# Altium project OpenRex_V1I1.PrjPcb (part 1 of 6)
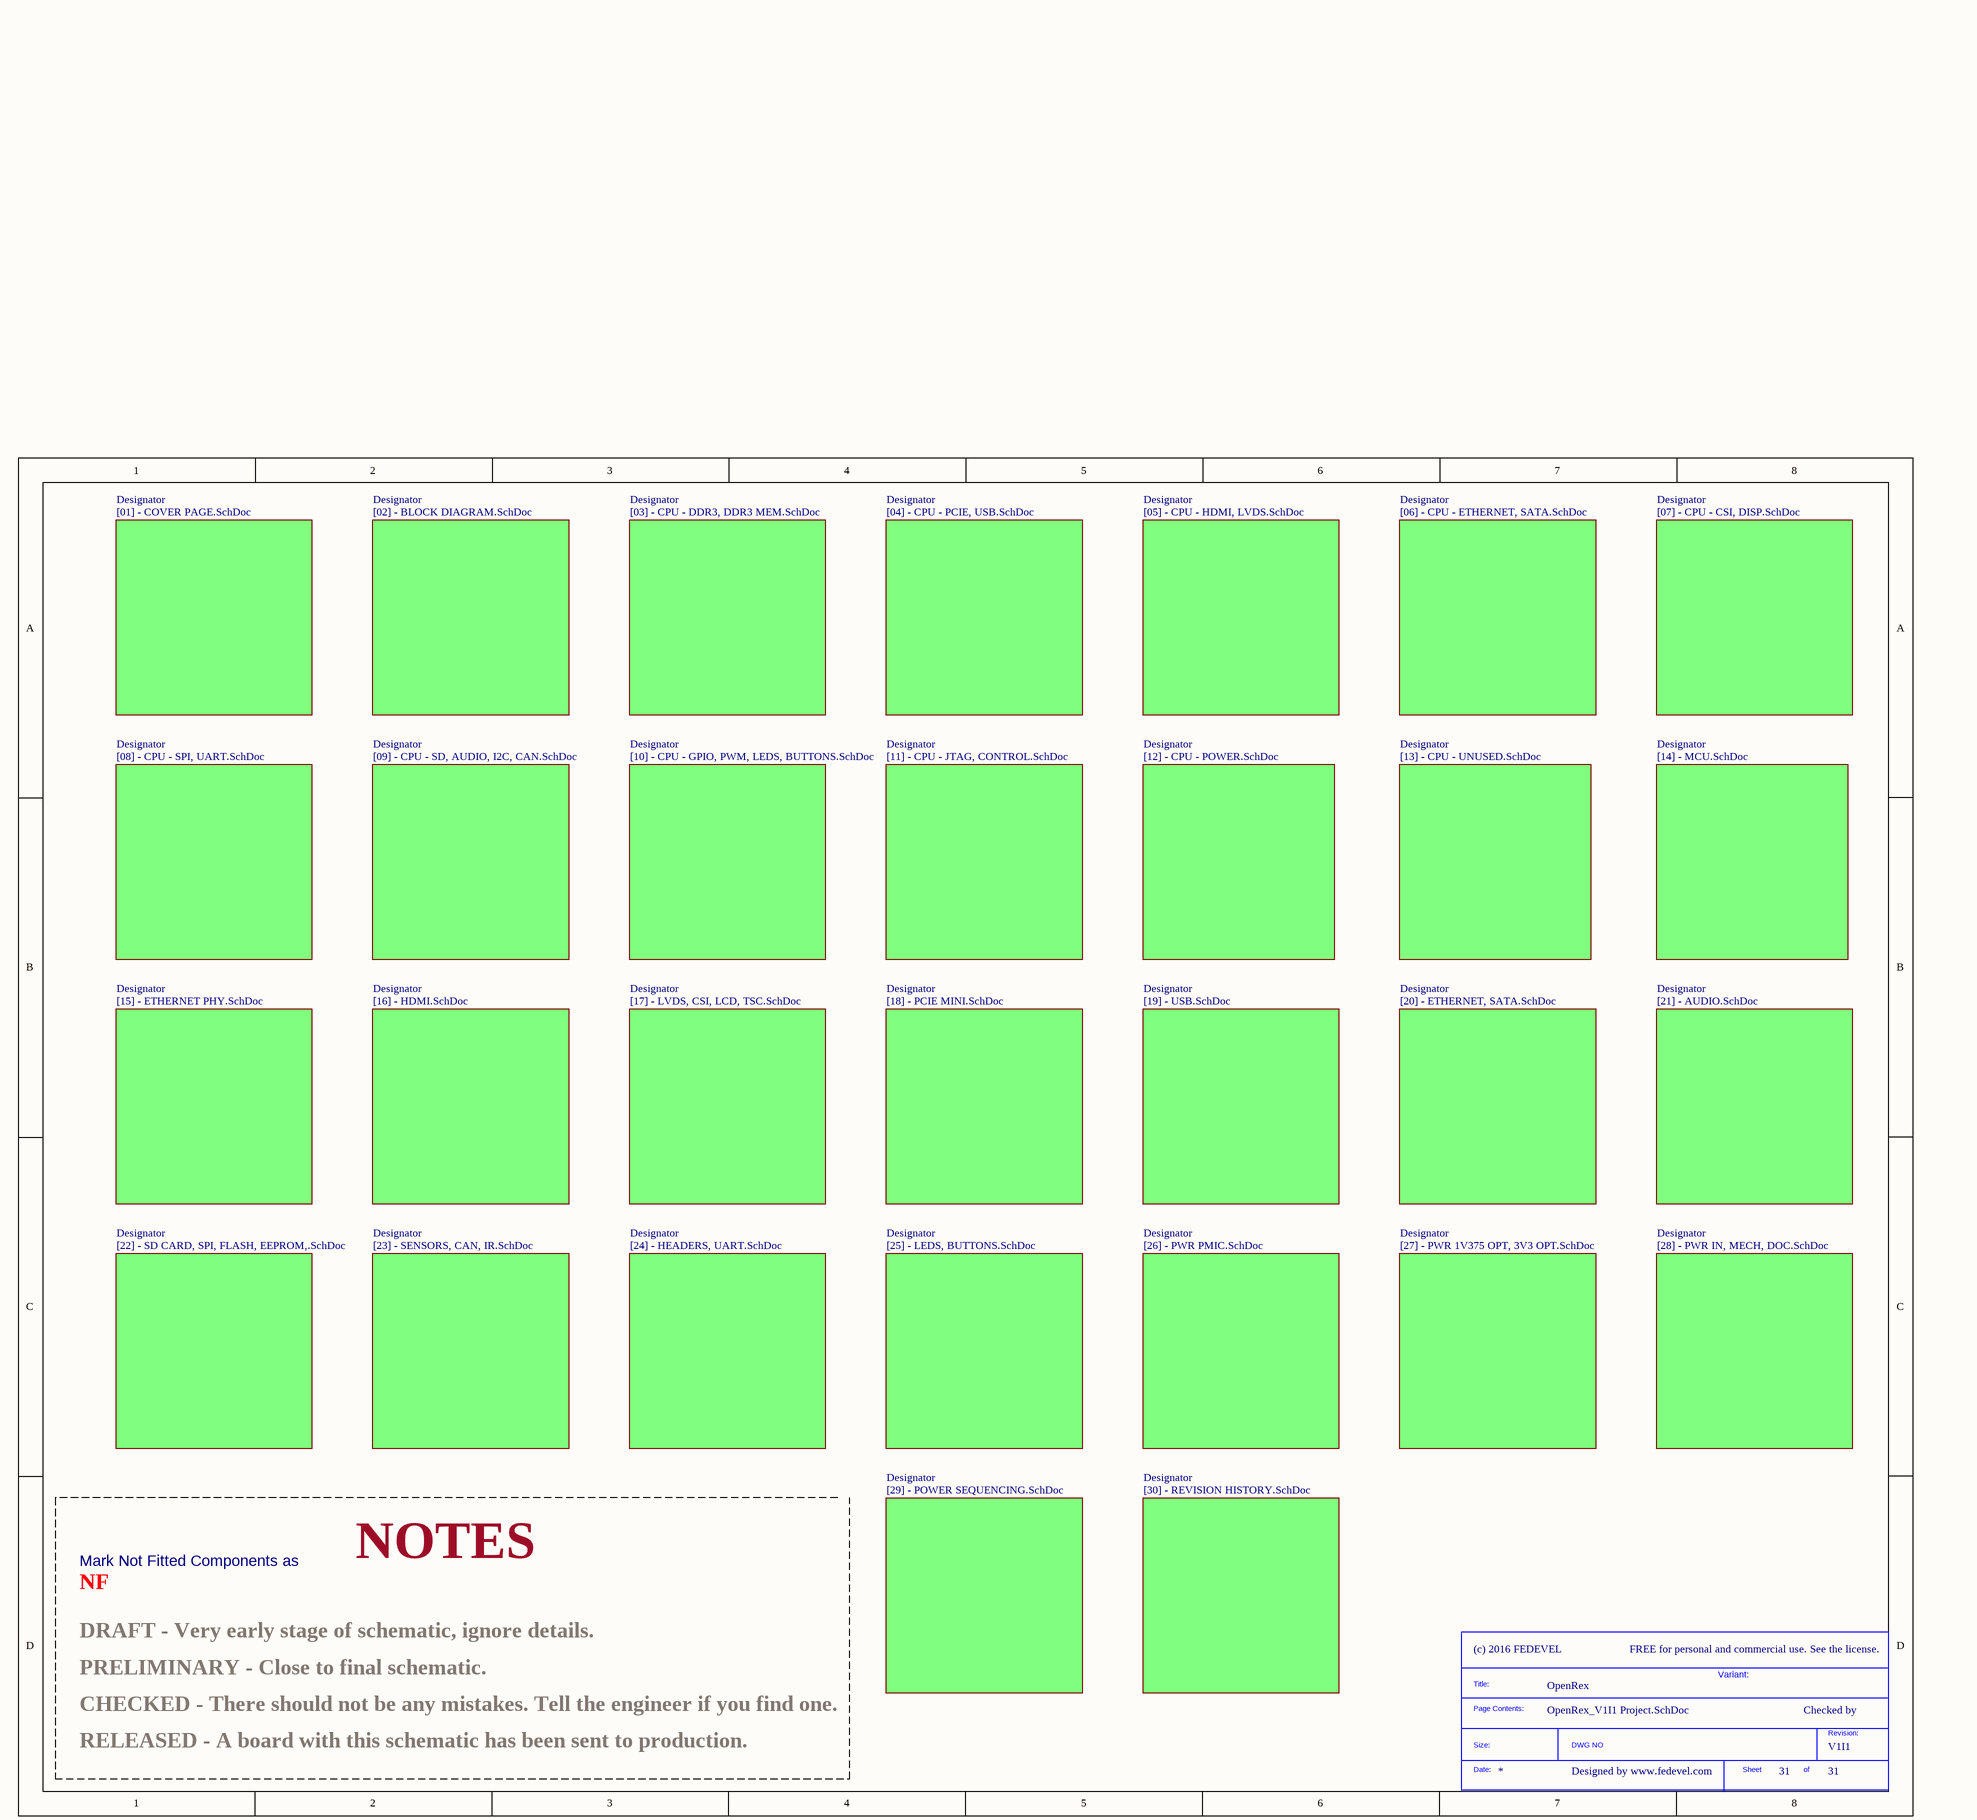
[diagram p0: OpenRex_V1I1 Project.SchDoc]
VersionRevision: V1I1; Project: OpenRex; NotFitted: NF; Company: (c) 2016 FEDEVEL; ClientWebsite: www.fedevel.com; ClientContactName: Robert Feranec; ClientContactEmail: robert.feranec@fedevel.com; ClientCompanyName: FEDEVEL Academy
31 sheets, 1116 parts. Net scope: flat (ports and power ports of the same name join across sheets).
Board file: OpenRex_V1I1_PCB.PcbDoc
Sheets:
  OpenRex_V1I1 Project.SchDoc
    Designator = [01] - COVER PAGE.SchDoc
    Designator = [02] - BLOCK DIAGRAM.SchDoc
    Designator = [17] - LVDS, CSI, LCD, TSC.SchDoc
    Designator = [04] - CPU - PCIE, USB.SchDoc
    Designator = [05] - CPU - HDMI, LVDS.SchDoc
    Designator = [06] - CPU - ETHERNET, SATA.SchDoc
    Designator = [08] - CPU - SPI, UART.SchDoc
    Designator = [10] - CPU - GPIO, PWM, LEDS, BUTTONS.SchDoc
    Designator = [09] - CPU - SD, AUDIO, I2C, CAN.SchDoc
    Designator = [03] - CPU - DDR3, DDR3 MEM.SchDoc
    Designator = [11] - CPU - JTAG, CONTROL.SchDoc
    Designator = [12] - CPU - POWER.SchDoc
    Designator = [18] - PCIE MINI.SchDoc
    Designator = [13] - CPU - UNUSED.SchDoc
    Designator = [15] - ETHERNET PHY.SchDoc
    Designator = [19] - USB.SchDoc
    Designator = [07] - CPU - CSI, DISP.SchDoc
    Designator = [14] - MCU.SchDoc
    Designator = [20] - ETHERNET, SATA.SchDoc
    Designator = [25] - LEDS, BUTTONS.SchDoc
    Designator = [26] - PWR PMIC.SchDoc
    Designator = [27] - PWR 1V375 OPT, 3V3 OPT.SchDoc
    Designator = [28] - PWR IN, MECH, DOC.SchDoc
    Designator = [22] - SD CARD, SPI, FLASH, EEPROM,.SchDoc
    Designator = [23] - SENSORS, CAN, IR.SchDoc
    Designator = [30] - REVISION HISTORY.SchDoc
    Designator = [16] - HDMI.SchDoc
    Designator = [21] - AUDIO.SchDoc
    Designator = [24] - HEADERS, UART.SchDoc
    Designator = [29] - POWER SEQUENCING.SchDoc

## Sheet OpenRex_V1I1 Project.SchDoc
size A3; DocumentNumber: 31; SheetNumber: 31; SheetTotal: 31; PageSetup: Record=PageOptions¦CenterHorizontal=True¦CenterVertical=True¦PrintScale=1.07¦XCorrection=1.00¦YCorrection=1.00¦PrintKind=1¦BorderSize=5000000¦LeftOffset=0¦BottomOffset=0¦Orientation=2¦PaperLength=1000¦PaperWidth=1000¦Scale=100¦PaperSource=7¦PrintQuality=600¦MediaType=1¦DitherType=10¦PaperKind=A3¦PrintScaleMode=1

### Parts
(Parts that share a designator on the sheet are numbered #1, #2 ... from top to bottom, then left to right.)
*#1  SDTitleBlock  (value not drawn)  (graphical)

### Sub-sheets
Designator = [01] - COVER PAGE.SchDoc: no entries
Designator = [02] - BLOCK DIAGRAM.SchDoc: no entries
Designator = [17] - LVDS, CSI, LCD, TSC.SchDoc: no entries
Designator = [04] - CPU - PCIE, USB.SchDoc: no entries
Designator = [05] - CPU - HDMI, LVDS.SchDoc: no entries
Designator = [06] - CPU - ETHERNET, SATA.SchDoc: no entries
Designator = [08] - CPU - SPI, UART.SchDoc: no entries
Designator = [10] - CPU - GPIO, PWM, LEDS, BUTTONS.SchDoc: no entries
Designator = [09] - CPU - SD, AUDIO, I2C, CAN.SchDoc: no entries
Designator = [03] - CPU - DDR3, DDR3 MEM.SchDoc: no entries
Designator = [11] - CPU - JTAG, CONTROL.SchDoc: no entries
Designator = [12] - CPU - POWER.SchDoc: no entries
Designator = [18] - PCIE MINI.SchDoc: no entries
Designator = [13] - CPU - UNUSED.SchDoc: no entries
Designator = [15] - ETHERNET PHY.SchDoc: no entries
Designator = [19] - USB.SchDoc: no entries
Designator = [07] - CPU - CSI, DISP.SchDoc: no entries
Designator = [14] - MCU.SchDoc: no entries
Designator = [20] - ETHERNET, SATA.SchDoc: no entries
Designator = [25] - LEDS, BUTTONS.SchDoc: no entries
Designator = [26] - PWR PMIC.SchDoc: no entries
Designator = [27] - PWR 1V375 OPT, 3V3 OPT.SchDoc: no entries
Designator = [28] - PWR IN, MECH, DOC.SchDoc: no entries
Designator = [22] - SD CARD, SPI, FLASH, EEPROM,.SchDoc: no entries
Designator = [23] - SENSORS, CAN, IR.SchDoc: no entries
Designator = [30] - REVISION HISTORY.SchDoc: no entries
Designator = [16] - HDMI.SchDoc: no entries
Designator = [21] - AUDIO.SchDoc: no entries
Designator = [24] - HEADERS, UART.SchDoc: no entries
Designator = [29] - POWER SEQUENCING.SchDoc: no entries

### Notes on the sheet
- NF
- Mark Not Fitted Components as
- NOTES
- DRAFT - Very early stage of schematic, ignore details.
- FREE for personal and commercial use. See the license.
- PRELIMINARY - Close to final schematic.
- CHECKED - There should not be any mistakes. Tell the engineer if you find one.
- Variant:
- Checked by
- RELEASED - A board with this schematic has been sent to production.
- Designed by www.fedevel.com

## Sheet [01] - COVER PAGE.SchDoc
size A3; DocumentNumber: 1; SheetNumber: 1; SheetTotal: 31
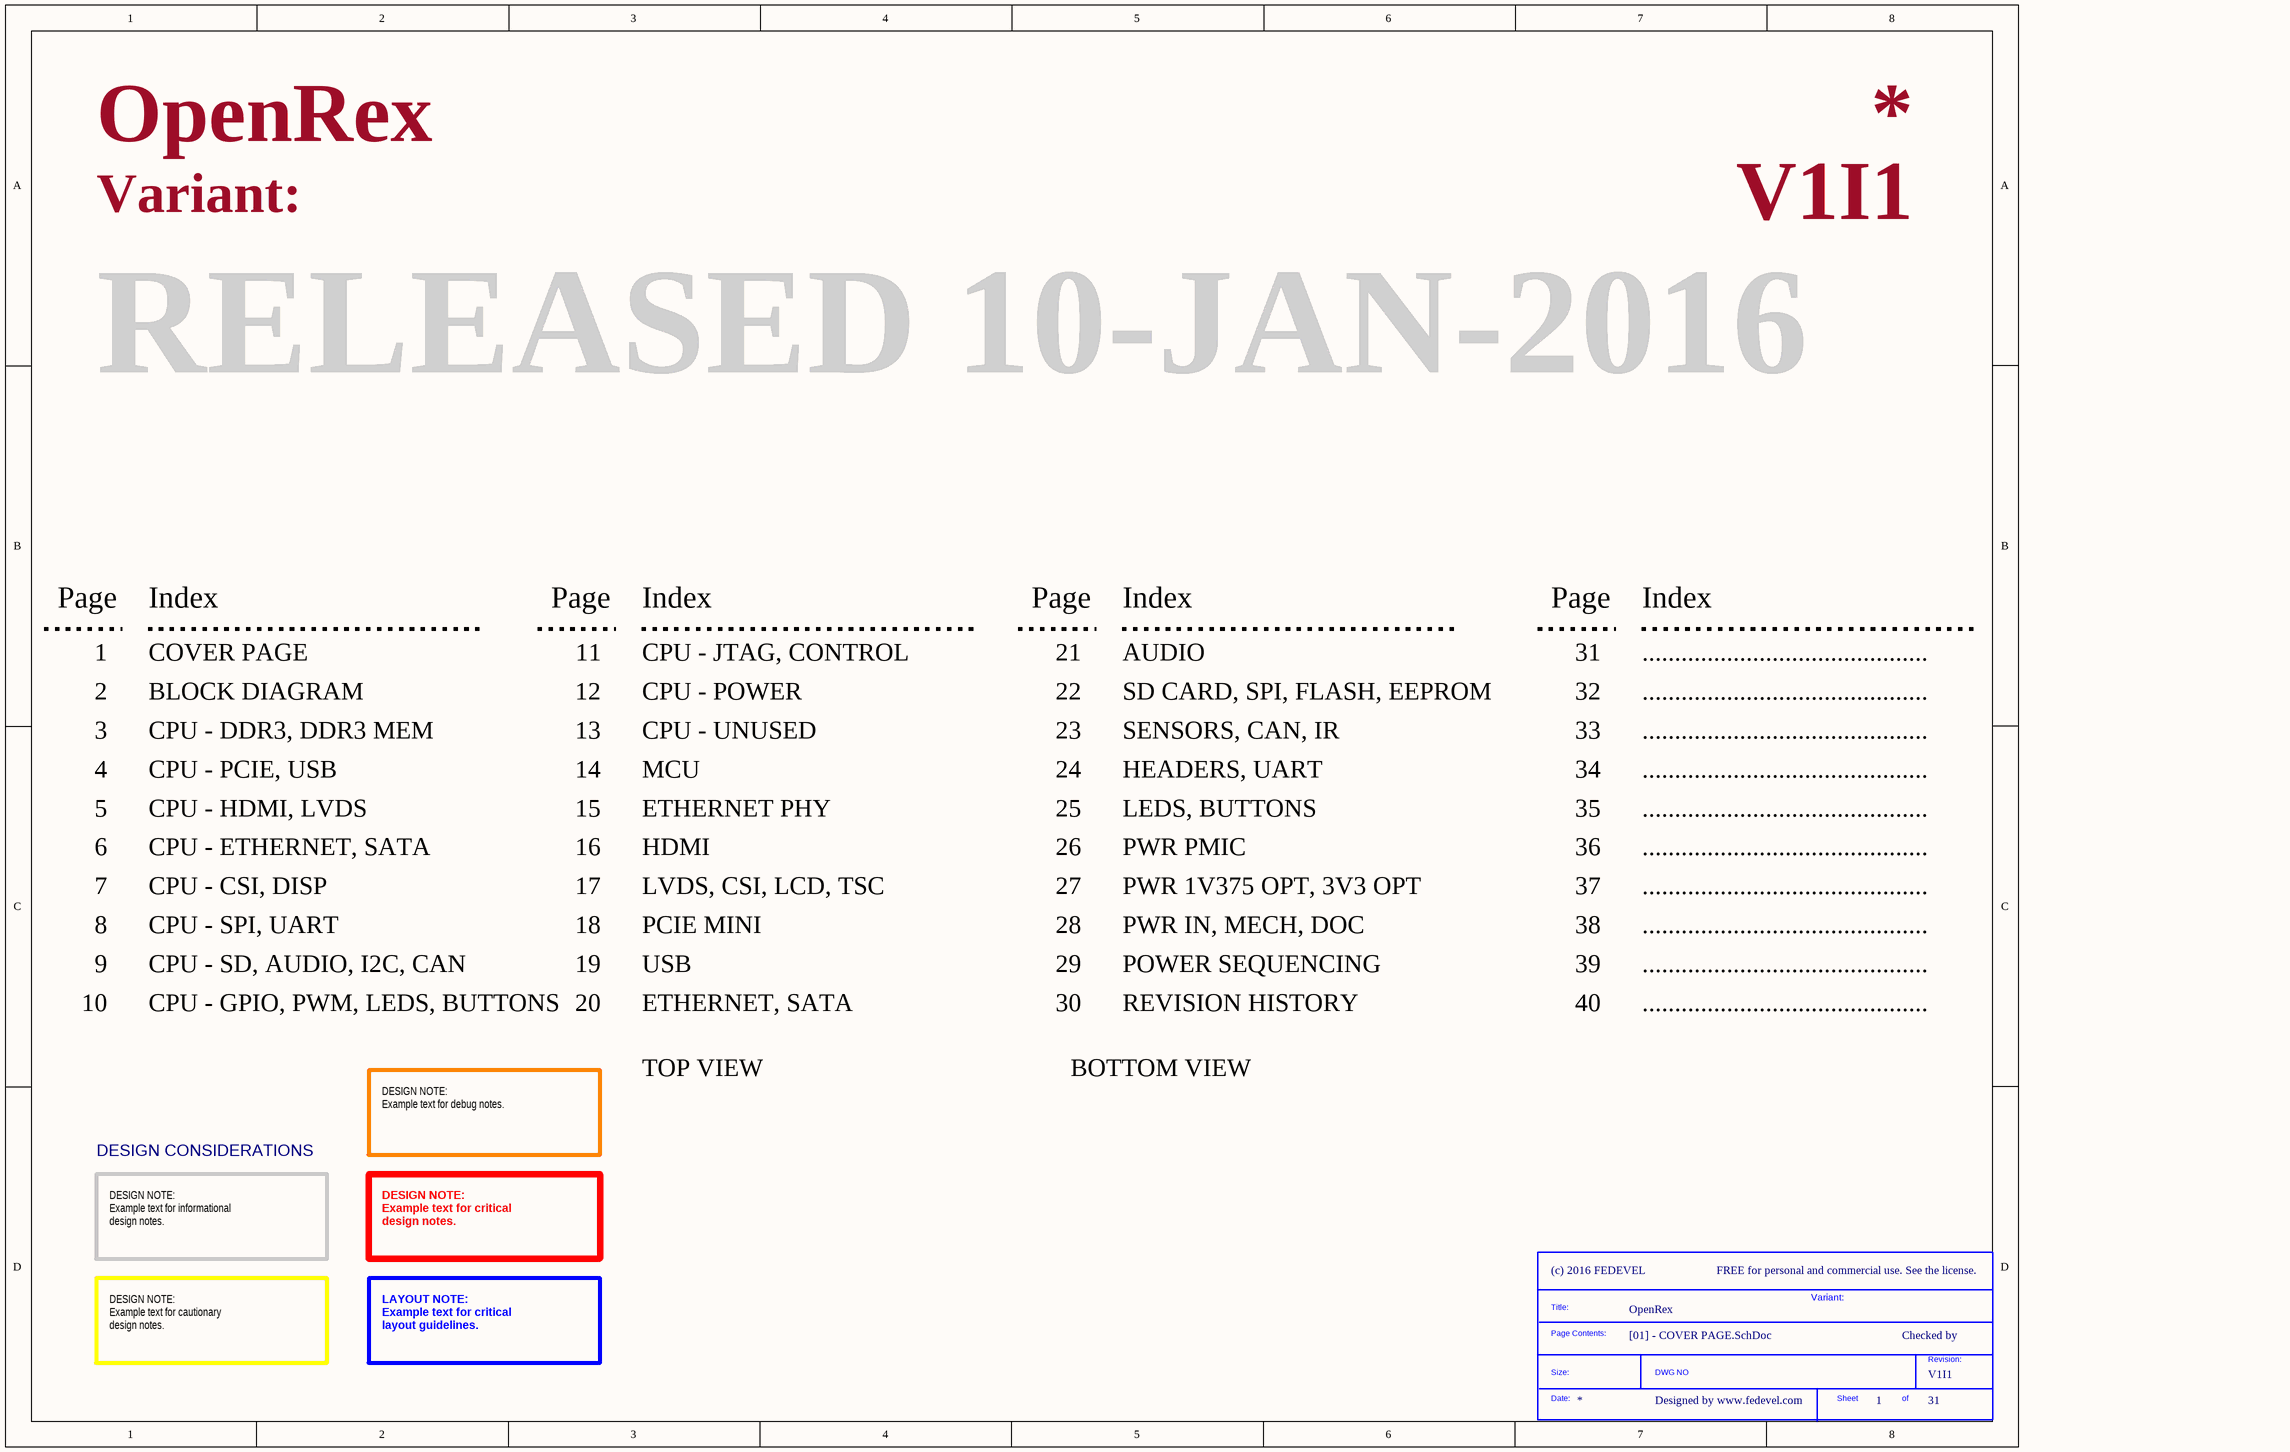
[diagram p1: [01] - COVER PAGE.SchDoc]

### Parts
(Parts that share a designator on the sheet are numbered #1, #2 ... from top to bottom, then left to right.)
*#2  SDTitleBlock  (value not drawn)  (graphical)

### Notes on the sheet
- Variant:
- RELEASED 10-JAN-2016
- Page
- Index
- 1
- COVER PAGE
- 11
- CPU - JTAG, CONTROL
- 21
- AUDIO
- 31
- ............................................
- 2
- 3
- BLOCK DIAGRAM
- CPU - DDR3, DDR3 MEM
- 12
- 13
- CPU - POWER
- CPU - UNUSED
- 22
- 23
- SD CARD, SPI, FLASH, EEPROM
- SENSORS, CAN, IR
- 32
- 33
- 4
- 5
- CPU - PCIE, USB
- CPU - HDMI, LVDS
- 14
- 15
- MCU
- ETHERNET PHY
- 24
- 25
- HEADERS, UART
- LEDS, BUTTONS
- 34
- 35
- 6
- CPU - ETHERNET, SATA
- 16
- HDMI
- 26
- PWR PMIC
- 36
- 7
- 8
- CPU - SPI, UART
- CPU - CSI, DISP
- 17
- 18
- LVDS, CSI, LCD, TSC
- PCIE MINI
- 27
- 28
- PWR 1V375 OPT, 3V3 OPT
- PWR IN, MECH, DOC
- 37
- 38
- 9
- 10
- CPU - SD, AUDIO, I2C, CAN
- CPU - GPIO, PWM, LEDS, BUTTONS
- 19
- 20
- USB
- ETHERNET, SATA
- 29
- 30
- POWER SEQUENCING
- REVISION HISTORY
- 39
- 40
- TOP VIEW
- BOTTOM VIEW
- DESIGN NOTE:
  Example text for debug notes.
- DESIGN CONSIDERATIONS
- DESIGN NOTE:
  Example text for informational
  design notes.
- DESIGN NOTE:
  Example text for critical
  design notes.
- FREE for personal and commercial use. See the license.
- Checked by
- DESIGN NOTE:
  Example text for cautionary
  design notes.
- LAYOUT NOTE:
  Example text for critical
  layout guidelines.
- Designed by www.fedevel.com

## Sheet [02] - BLOCK DIAGRAM.SchDoc
size A2; DocumentNumber: 2; SheetNumber: 2; SheetTotal: 31; PageSetup: Record=PageOptions¦CenterHorizontal=True¦CenterVertical=True¦PrintScale=0.52¦XCorrection=1.00¦YCorrection=1.00¦PrintKind=1¦BorderSize=5000000¦LeftOffset=0¦BottomOffset=0¦Orientation=2¦PaperLength=1000¦PaperWidth=1000¦Scale=100¦PaperSource=4¦PrintQuality=600¦MediaType=1¦DitherType=10¦PrintScaleMode=1¦PaperKind=A4¦PaperIndex=9
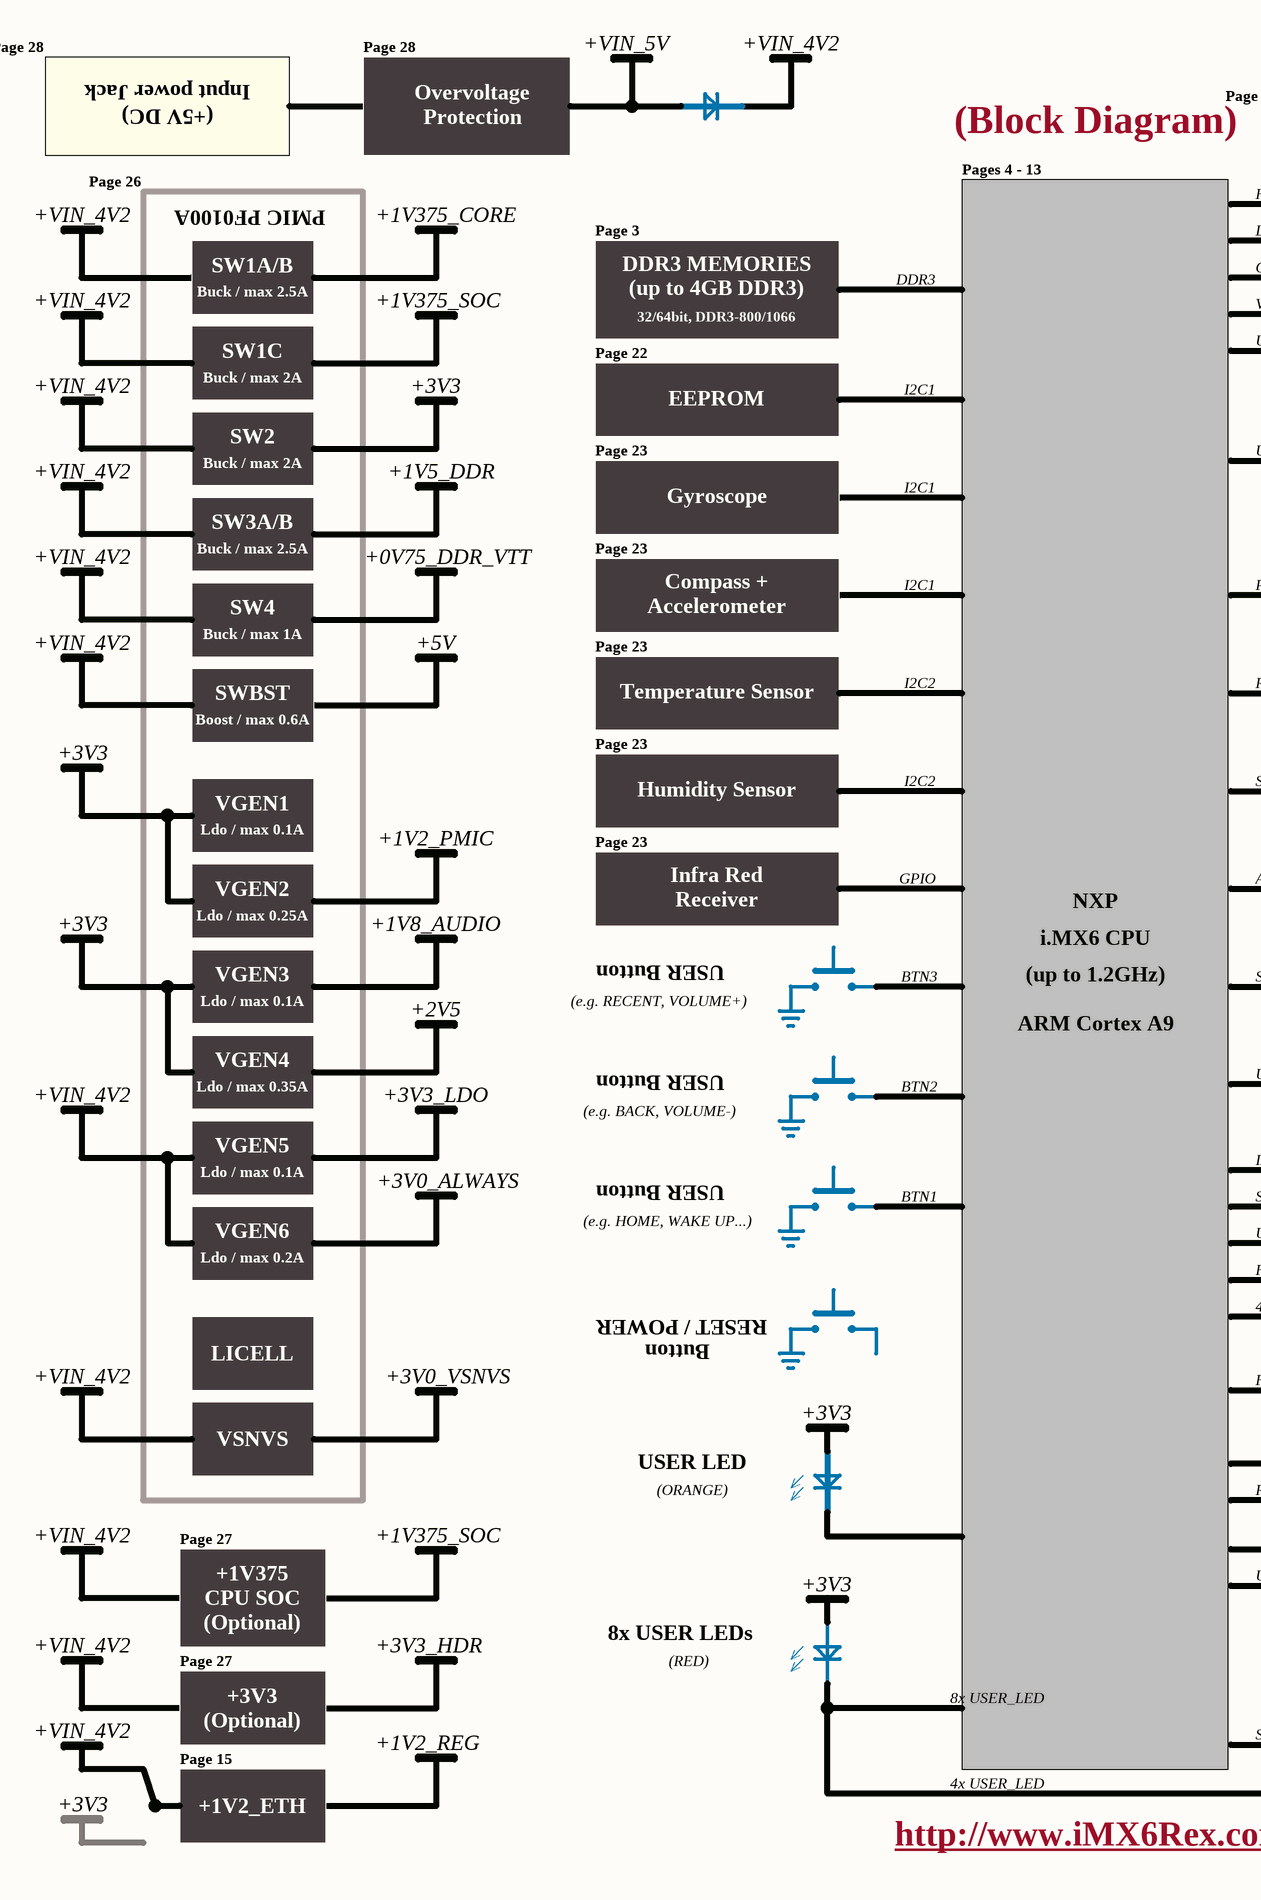
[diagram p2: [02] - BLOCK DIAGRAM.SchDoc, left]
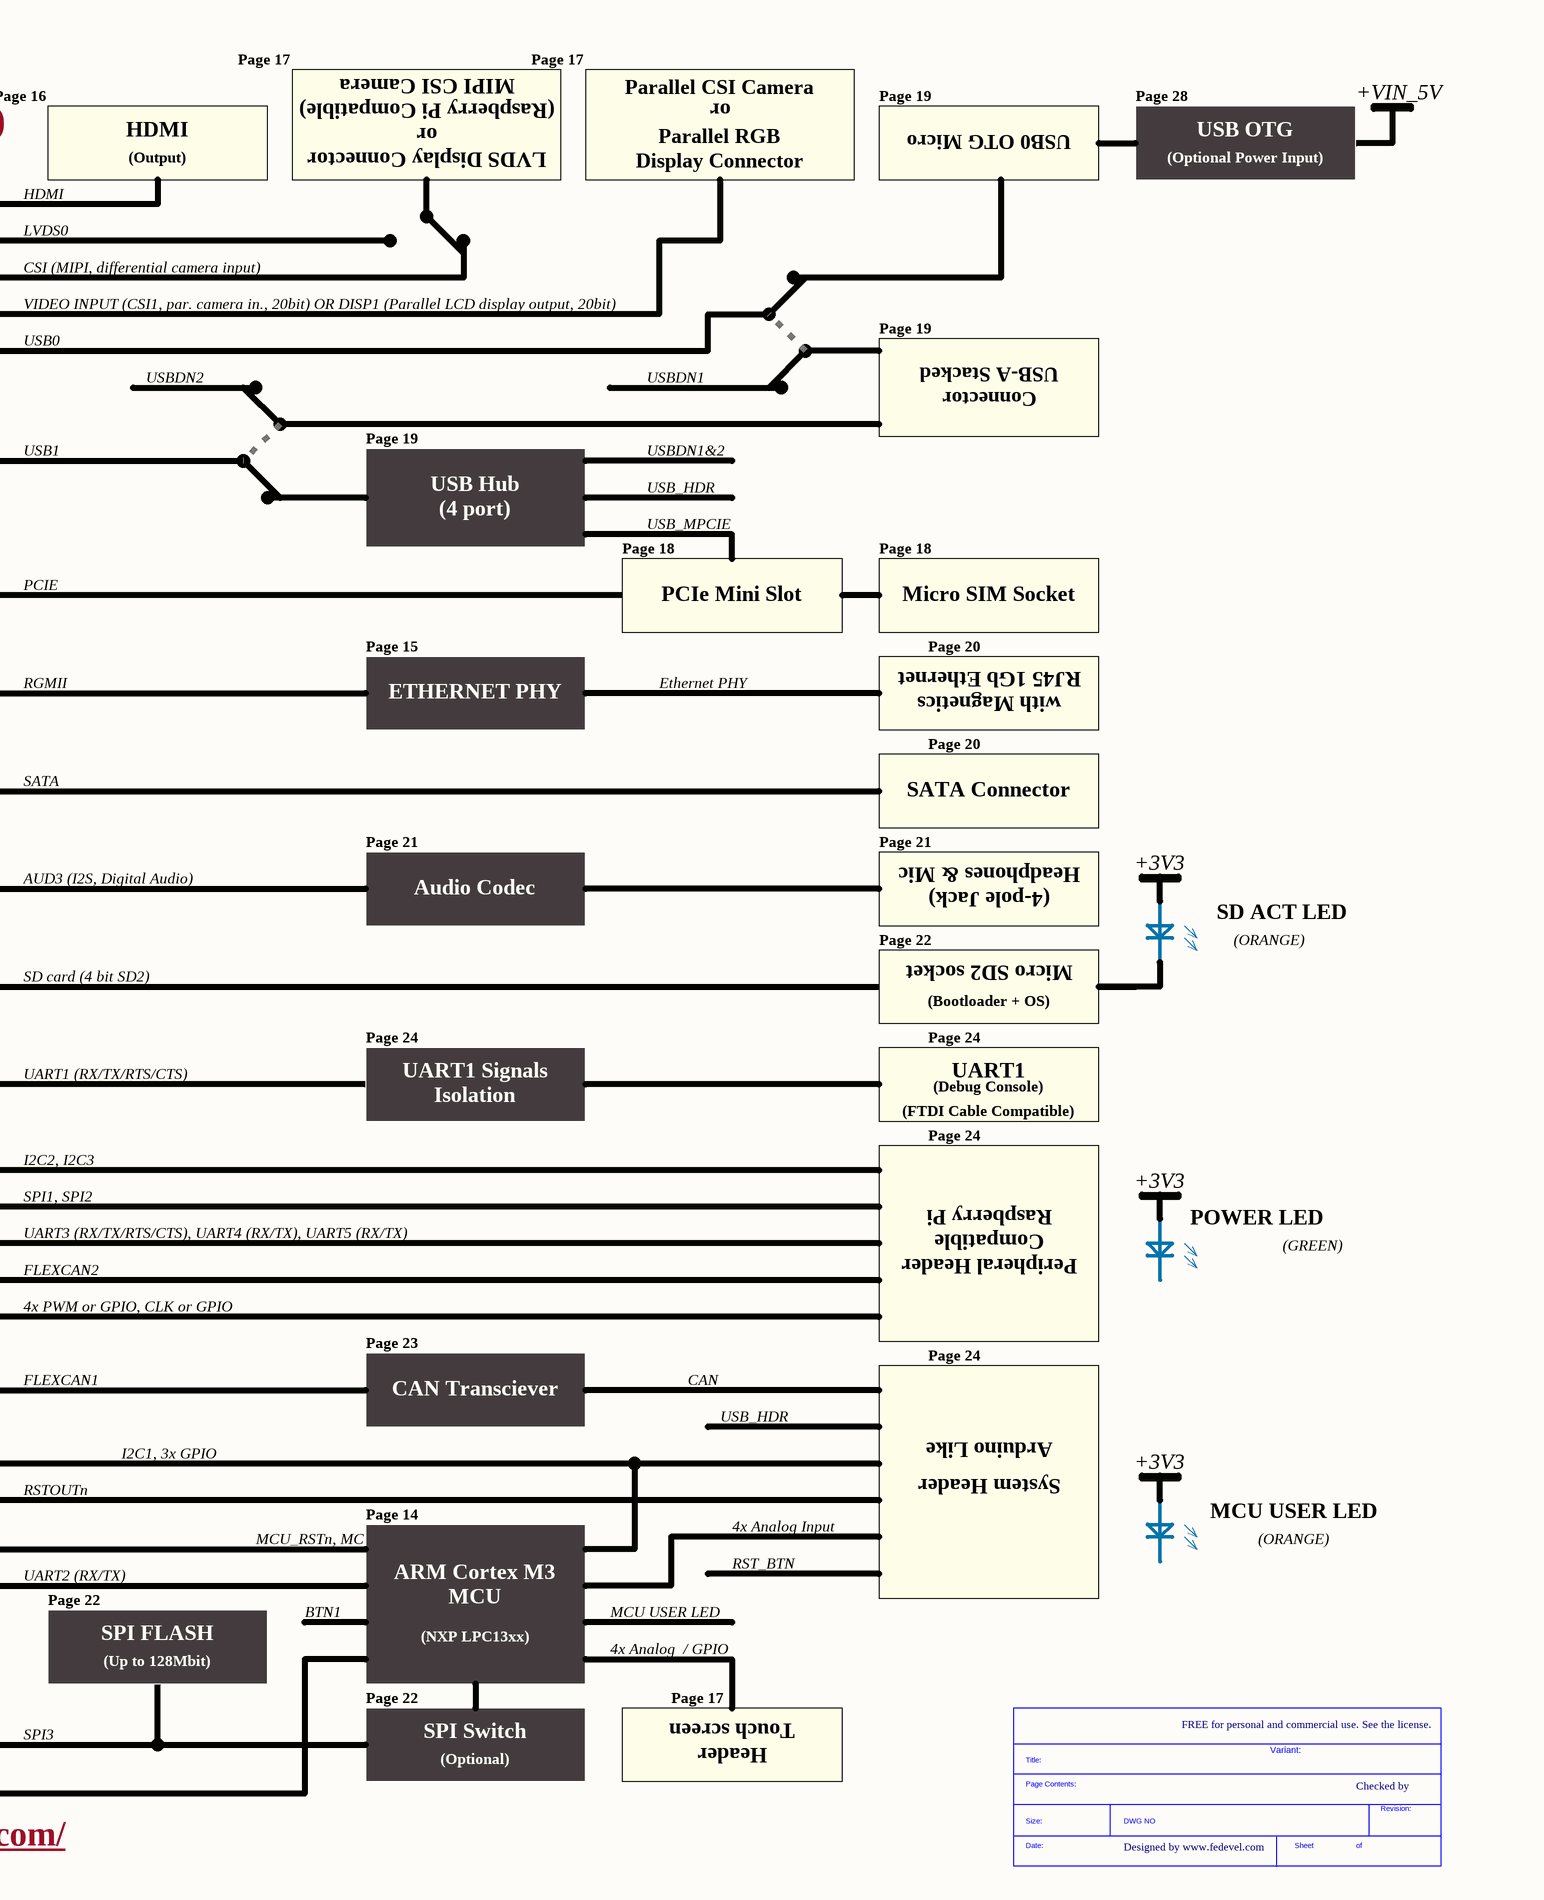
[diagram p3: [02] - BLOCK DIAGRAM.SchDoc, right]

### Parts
(Parts that share a designator on the sheet are numbered #1, #2 ... from top to bottom, then left to right.)
*#3  SDTitleBlock  (value not drawn)  (graphical)

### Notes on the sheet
- Page 28
- +VIN_5V
- +VIN_4V2
- Page 17
- MIPI CSI Camera
- Parallel CSI Camera
- Input power Jack
- (+5V DC)
- Overvoltage
- Protection
- (Block Diagram)
- Page 16
- HDMI
- (Raspberry Pi Compatible)
- or
- Parallel RGB
- Page 19
- USB0 OTG Micro
- USB OTG
- Page 26
- PMIC PF0100A
- Pages 4 - 13
- (Output)
- LVDS Display Connector
- Display Connector
- (Optional Power Input)
- SW1A/B
- +1V375_CORE
- Page 3
- DDR3 MEMORIES
- LVDS0
- CSI (MIPI, differential camera input)
- Buck / max 2.5A
- +1V375_SOC
- 32/64bit, DDR3-800/1066
- (up to 4GB DDR3)
- DDR3
- VIDEO INPUT (CSI1, par. camera in., 20bit) OR DISP1 (Parallel LCD display output, 20bit)
- SW1C
- Buck / max 2A
- +3V3
- Page 22
- I2C1
- USB0
- USBDN2
- USBDN1
- USB-A Stacked
- SW2
- Page 23
- EEPROM
- USB1
- USBDN1&2
- Connector
- SW3A/B
- +1V5_DDR
- Gyroscope
- USB Hub
- (4 port)
- USB_HDR
- +0V75_DDR_VTT
- Page 18
- USB_MPCIE
- SW4
- Buck / max 1A
- Compass +
- Accelerometer
- PCIE
- PCIe Mini Slot
- Micro SIM Socket
- SWBST
- +5V
- Temperature Sensor
- I2C2
- RGMII
- Page 15
- ETHERNET PHY
- Ethernet PHY
- Page 20
- RJ45 1Gb Ethernet
- Boost / max 0.6A
- with Magnetics
- VGEN1
- Humidity Sensor
- SATA
- SATA Connector
- Ldo / max 0.1A
- VGEN2
- +1V2_PMIC
- Infra Red
- GPIO
- AUD3 (I2S, Digital Audio)
- Page 21
- Headphones & Mic
- Ldo / max 0.25A
- +1V8_AUDIO
- Receiver
- NXP
- i.MX6 CPU
- Audio Codec
- (4-pole Jack)
- (ORANGE)
- SD ACT LED
- VGEN3
- (e.g. RECENT, VOLUME+)
- USER Button
- BTN3
- (up to 1.2GHz)
- SD card (4 bit SD2)
- Micro SD2 socket
- (Bootloader + OS)
- VGEN4
- +2V5
- ARM Cortex A9
- Page 24
- Ldo / max 0.35A
- +3V3_LDO
- (e.g. BACK, VOLUME-)
- BTN2
- UART1 (RX/TX/RTS/CTS)
- UART1 Signals
- Isolation
- UART1
- (Debug Console)
- (FTDI Cable Compatible)
- VGEN5
- +3V0_ALWAYS
- I2C2, I2C3
- VGEN6
- (e.g. HOME, WAKE UP...)
- BTN1
- SPI1, SPI2
- UART3 (RX/TX/RTS/CTS), UART4 (RX/TX), UART5 (RX/TX)
- Raspberry Pi
- Compatible
- POWER LED
- (GREEN)
- Ldo / max 0.2A
- 4x PWM or GPIO, CLK or GPIO
- FLEXCAN2
- Peripheral Header
- LICELL
- RESET / POWER
- Button
- VSNVS
- +3V0_VSNVS
- FLEXCAN1
- CAN Transciever
- CAN
- USER LED
- RSTOUTn
- I2C1, 3x GPIO
- System Header
- Arduino Like
- Page 27
- MCU_RSTn, MCU_ISPn, SWD debug
- Page 14
- 4x Analog Input
- MCU USER LED
- +1V375
- CPU SOC
- (Optional)
- UART2 (RX/TX)
- ARM Cortex M3
- MCU
- RST_BTN
- +3V3_HDR
- (RED)
- 8x USER LEDs
- SPI FLASH
- (Up to 128Mbit)
- (NXP LPC13xx)
- 4x Analog  / GPIO
- 8x USER_LED
- SPI3
- SPI Switch
- Touch screen
- FREE for personal and commercial use. See the license.
- +1V2_ETH
- +1V2_REG
- 4x USER_LED
- Header
- Variant:
- Checked by
- http://www.iMX6Rex.com/
- Designed by www.fedevel.com

## Sheet [17] - LVDS, CSI, LCD, TSC.SchDoc
size A2; DocumentNumber: 17; SheetNumber: 17; SheetTotal: 31
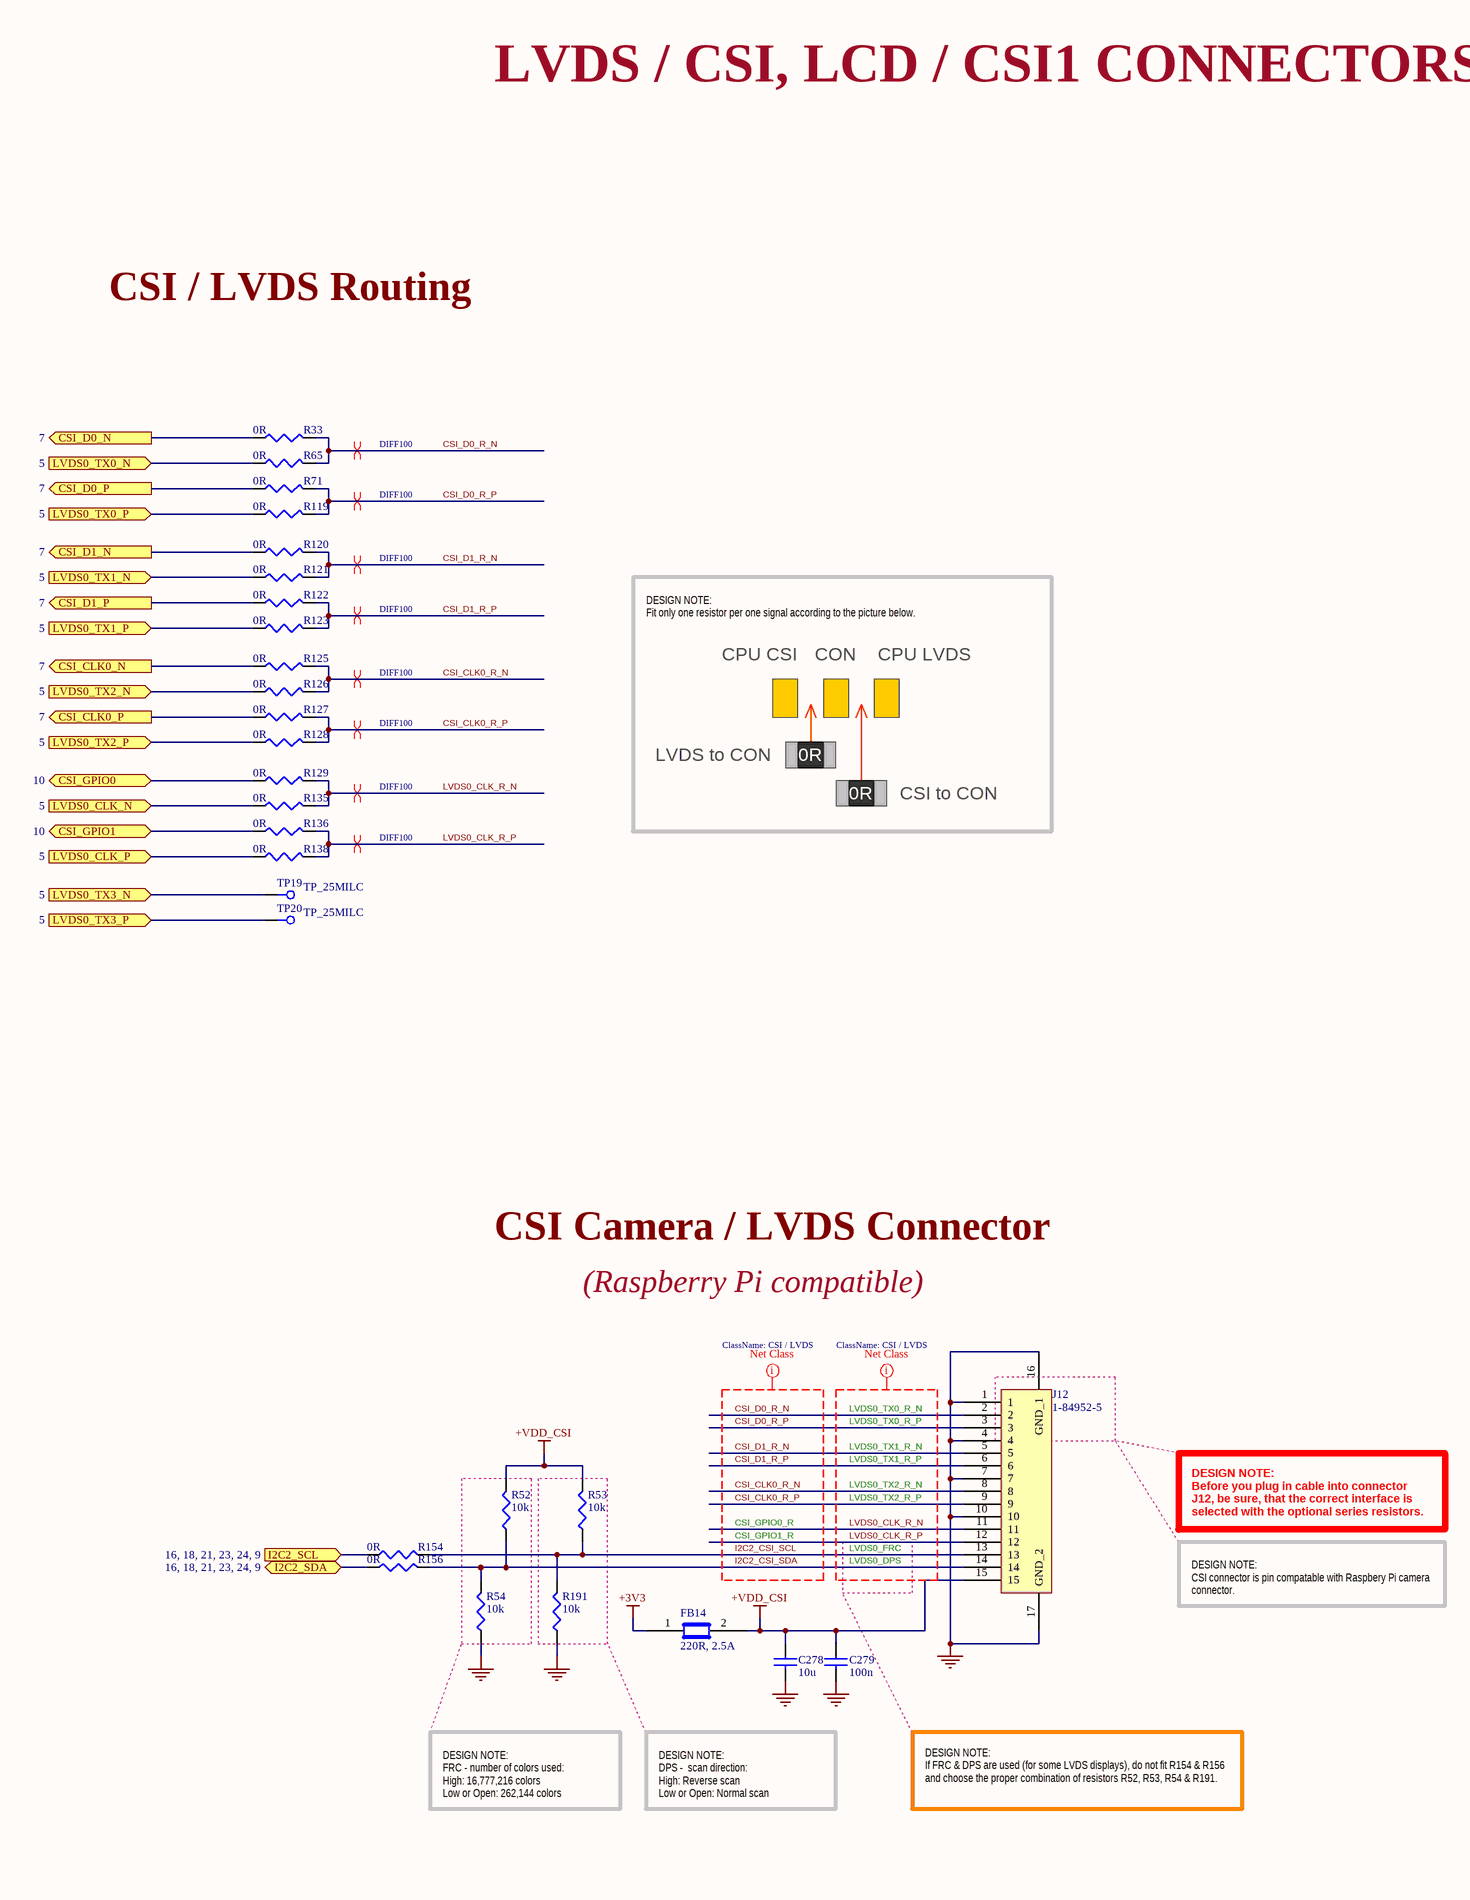
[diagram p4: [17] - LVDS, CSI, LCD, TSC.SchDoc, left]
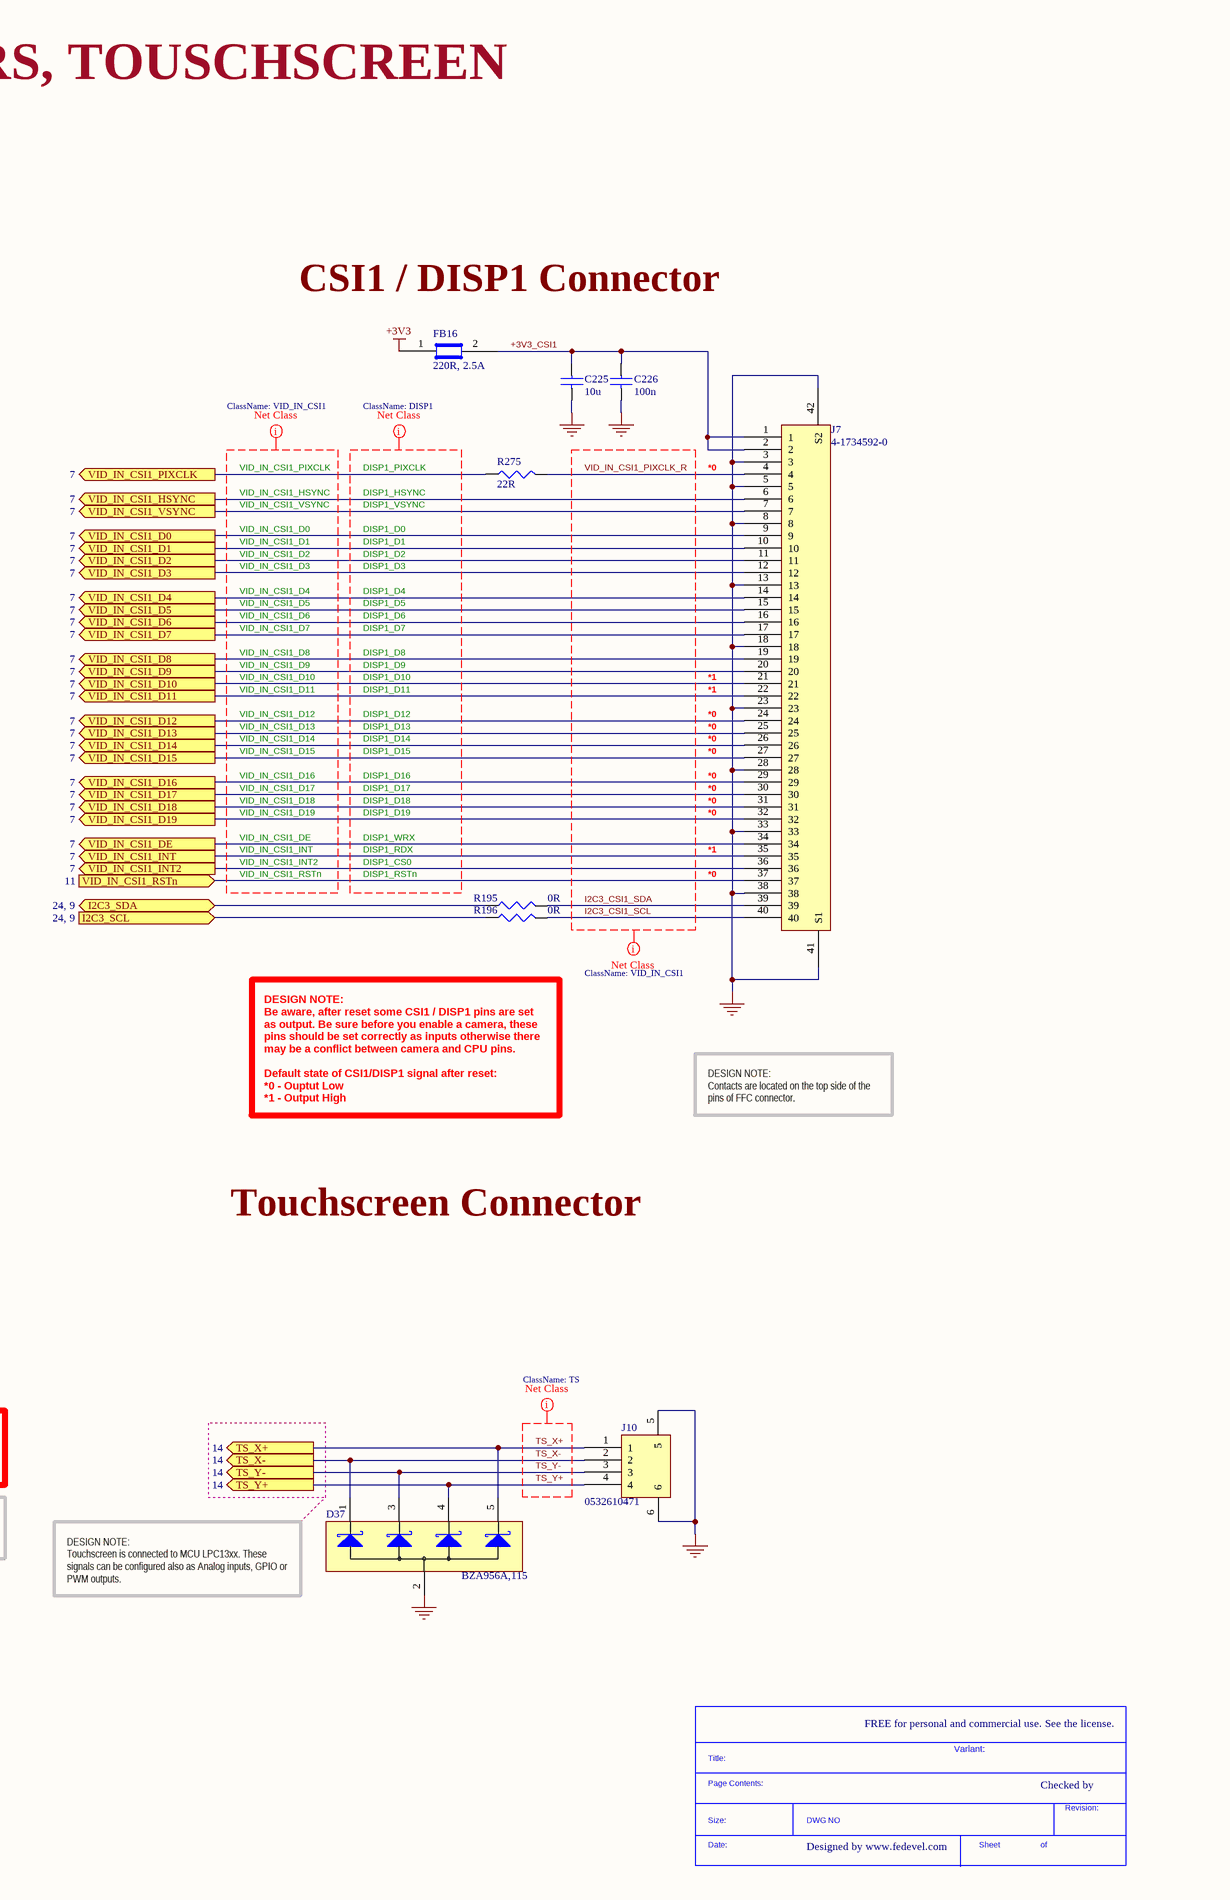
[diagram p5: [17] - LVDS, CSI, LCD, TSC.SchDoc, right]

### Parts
(Parts that share a designator on the sheet are numbered #1, #2 ... from top to bottom, then left to right.)
*#4  SDTitleBlock  (value not drawn)  (graphical)
C225  10u  [C0603]
C226  100n  [C0402]
C278  10u  [C0603]
C279  100n  [C0402]
D37  BZA956A,115  [SOT665]
FB14  220R, 2.5A  [C0603]
FB16  220R, 2.5A  [C0603]
J7  4-1734592-0  [4-1734592-0]
J10  0532610471  [0532610471]
J12  1-84952-5  [ZIF_RA_BOTTOM_15x1mm]
R33  0R  [R0402]
R52  10k  [R0402]
R53  10k  [R0402]
R54  10k  [R0402]
R65  0R  [R0402]
R71  0R  [R0402]
R119  0R  [R0402]
R120  0R  [R0402]
R121  0R  [R0402]
R122  0R  [R0402]
R123  0R  [R0402]
R125  0R  [R0402]
R126  0R  [R0402]
R127  0R  [R0402]
R128  0R  [R0402]
R129  0R  [R0402]
R135  0R  [R0402]
R136  0R  [R0402]
R138  0R  [R0402]
R154  0R  [R0402]
R156  0R  [R0402]
R191  10k  [R0402]
R195  0R  [R0402]
R196  0R  [R0402]
R275  22R  [R0402]
TP19  TP_25MILC  [TP_25C]  (no BOM)
TP20  TP_25MILC  [TP_25C]  (no BOM)

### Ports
CSI_CLK0_N (out, see 7), CSI_CLK0_P (out, see 7), CSI_D0_N (out, see 7), CSI_D0_P (out, see 7), CSI_D1_N (out, see 7), CSI_D1_P (out, see 7), CSI_GPIO0 (bidir, see 10), CSI_GPIO1 (bidir, see 10), I2C2_SCL (see 16, 18, 21, 23, 24, 9), I2C2_SDA (bidir, see 16, 18, 21, 23, 24, 9), I2C3_SCL (see 24, 9), I2C3_SDA (bidir, see 24, 9), LVDS0_CLK_N (in, see 5), LVDS0_CLK_P (in, see 5), LVDS0_TX0_N (in, see 5), LVDS0_TX0_P (in, see 5), LVDS0_TX1_N (in, see 5), LVDS0_TX1_P (in, see 5), LVDS0_TX2_N (in, see 5), LVDS0_TX2_P (in, see 5), LVDS0_TX3_N (in, see 5), LVDS0_TX3_P (in, see 5), TS_X+ (out, see 14), TS_X- (out, see 14), TS_Y+ (out, see 14), TS_Y- (out, see 14), VID_IN_CSI1_D0 (out, see 7), VID_IN_CSI1_D1 (out, see 7), VID_IN_CSI1_D2 (out, see 7), VID_IN_CSI1_D3 (out, see 7), VID_IN_CSI1_D4 (out, see 7), VID_IN_CSI1_D5 (out, see 7), VID_IN_CSI1_D6 (out, see 7), VID_IN_CSI1_D7 (out, see 7), VID_IN_CSI1_D8 (out, see 7), VID_IN_CSI1_D9 (out, see 7), VID_IN_CSI1_D10 (out, see 7), VID_IN_CSI1_D11 (out, see 7), VID_IN_CSI1_D12 (out, see 7), VID_IN_CSI1_D13 (out, see 7), VID_IN_CSI1_D14 (out, see 7), VID_IN_CSI1_D15 (out, see 7), VID_IN_CSI1_D16 (out, see 7), VID_IN_CSI1_D17 (out, see 7), VID_IN_CSI1_D18 (out, see 7), VID_IN_CSI1_D19 (out, see 7), VID_IN_CSI1_DE (out, see 7), VID_IN_CSI1_HSYNC (out, see 7), VID_IN_CSI1_INT2 (out, see 7), VID_IN_CSI1_INT (out, see 7), VID_IN_CSI1_PIXCLK (out, see 7), VID_IN_CSI1_RSTn (in, see 11), VID_IN_CSI1_VSYNC (out, see 7)

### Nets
+3V3: FB14.1 FB16.1
+VDD_CSI: C278.1 C279.1 FB14.2 J12.15 R52.2 R53.2
GND: C225.2 C226.2 C278.2 C279.2 D37.2 J7.3 J7.5 J7.8 J7.13 J7.18 J7.23 J7.28 J7.33 J7.38 J7.41(S1) J7.42(S2) J10.5 J10.6 J12.1 J12.4 J12.7 J12.10 J12.16(GND_1) J12.17(GND_2) R54.1 R191.1
+3V3_CSI1: C225.1 C226.1 FB16.2 J7.1 J7.2
CSI_CLK0_N: R125.1 ; port CSI_CLK0_N
CSI_CLK0_P: R127.1 ; port CSI_CLK0_P
CSI_CLK0_R_N: J12.8 R125.2 R126.2
CSI_CLK0_R_P: J12.9 R127.2 R128.2
CSI_D0_N: R33.1 ; port CSI_D0_N
CSI_D0_P: R71.1 ; port CSI_D0_P
CSI_D0_R_N: J12.2 R33.2 R65.2
CSI_D0_R_P: J12.3 R71.2 R119.2
CSI_D1_N: R120.1 ; port CSI_D1_N
CSI_D1_P: R122.1 ; port CSI_D1_P
CSI_D1_R_N: J12.5 R120.2 R121.2
CSI_D1_R_P: J12.6 R122.2 R123.2
CSI_GPIO0: R129.1 ; port CSI_GPIO0
CSI_GPIO1: R136.1 ; port CSI_GPIO1
I2C2_CSI_SCL: J12.13 R53.1 R154.2 R191.2
I2C2_CSI_SDA: J12.14 R52.1 R54.2 R156.2
I2C2_SCL: R154.1 ; port I2C2_SCL
I2C2_SDA: R156.1 ; port I2C2_SDA
I2C3_CSI1_SCL: J7.40 R196.1
I2C3_CSI1_SDA: J7.39 R195.1
I2C3_SCL: R196.2 ; port I2C3_SCL
I2C3_SDA: R195.2 ; port I2C3_SDA
LVDS0_CLK_N: R135.1 ; port LVDS0_CLK_N
LVDS0_CLK_P: R138.1 ; port LVDS0_CLK_P
LVDS0_CLK_R_N: J12.11 R129.2 R135.2
LVDS0_CLK_R_P: J12.12 R136.2 R138.2
LVDS0_TX0_N: R65.1 ; port LVDS0_TX0_N
LVDS0_TX0_P: R119.1 ; port LVDS0_TX0_P
LVDS0_TX1_N: R121.1 ; port LVDS0_TX1_N
LVDS0_TX1_P: R123.1 ; port LVDS0_TX1_P
LVDS0_TX2_N: R126.1 ; port LVDS0_TX2_N
LVDS0_TX2_P: R128.1 ; port LVDS0_TX2_P
LVDS0_TX3_N: TP19.1 ; port LVDS0_TX3_N
LVDS0_TX3_P: TP20.1 ; port LVDS0_TX3_P
TS_X+: D37.5 J10.1 ; port TS_X+
TS_X-: D37.1 J10.2 ; port TS_X-
TS_Y+: D37.4 J10.4 ; port TS_Y+
TS_Y-: D37.3 J10.3 ; port TS_Y-
VID_IN_CSI1_D0: J7.9 ; port VID_IN_CSI1_D0
VID_IN_CSI1_D1: J7.10 ; port VID_IN_CSI1_D1
VID_IN_CSI1_D2: J7.11 ; port VID_IN_CSI1_D2
VID_IN_CSI1_D3: J7.12 ; port VID_IN_CSI1_D3
VID_IN_CSI1_D4: J7.14 ; port VID_IN_CSI1_D4
VID_IN_CSI1_D5: J7.15 ; port VID_IN_CSI1_D5
VID_IN_CSI1_D6: J7.16 ; port VID_IN_CSI1_D6
VID_IN_CSI1_D7: J7.17 ; port VID_IN_CSI1_D7
VID_IN_CSI1_D8: J7.19 ; port VID_IN_CSI1_D8
VID_IN_CSI1_D9: J7.20 ; port VID_IN_CSI1_D9
VID_IN_CSI1_D10: J7.21 ; port VID_IN_CSI1_D10
VID_IN_CSI1_D11: J7.22 ; port VID_IN_CSI1_D11
VID_IN_CSI1_D12: J7.24 ; port VID_IN_CSI1_D12
VID_IN_CSI1_D13: J7.25 ; port VID_IN_CSI1_D13
VID_IN_CSI1_D14: J7.26 ; port VID_IN_CSI1_D14
VID_IN_CSI1_D15: J7.27 ; port VID_IN_CSI1_D15
VID_IN_CSI1_D16: J7.29 ; port VID_IN_CSI1_D16
VID_IN_CSI1_D17: J7.30 ; port VID_IN_CSI1_D17
VID_IN_CSI1_D18: J7.31 ; port VID_IN_CSI1_D18
VID_IN_CSI1_D19: J7.32 ; port VID_IN_CSI1_D19
VID_IN_CSI1_DE: J7.34 ; port VID_IN_CSI1_DE
VID_IN_CSI1_HSYNC: J7.6 ; port VID_IN_CSI1_HSYNC
VID_IN_CSI1_INT: J7.35 ; port VID_IN_CSI1_INT
VID_IN_CSI1_INT2: J7.36 ; port VID_IN_CSI1_INT2
VID_IN_CSI1_PIXCLK: R275.1 ; port VID_IN_CSI1_PIXCLK
VID_IN_CSI1_PIXCLK_R: J7.4 R275.2
VID_IN_CSI1_RSTn: J7.37 ; port VID_IN_CSI1_RSTn
VID_IN_CSI1_VSYNC: J7.7 ; port VID_IN_CSI1_VSYNC

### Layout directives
net class DISP1: (no net found under the mark)
net class VID_IN_CSI1: (no net found under the mark), I2C3_CSI1_SCL, I2C3_CSI1_SDA, VID_IN_CSI1_PIXCLK_R
differential pair; net class DIFF100: CSI_CLK0_R_N, CSI_CLK0_R_P, CSI_D0_R_N, CSI_D0_R_P, CSI_D1_R_N, CSI_D1_R_P, LVDS0_CLK_R_N, LVDS0_CLK_R_P
net class TS: TS_X+, TS_X-, TS_Y+, TS_Y-
net class CSI / LVDS: CSI_CLK0_R_N, CSI_CLK0_R_P, CSI_D0_R_N, CSI_D0_R_P, CSI_D1_R_N, CSI_D1_R_P, I2C2_CSI_SCL, I2C2_CSI_SDA, LVDS0_CLK_R_N, LVDS0_CLK_R_P

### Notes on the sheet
- LVDS / CSI, LCD / CSI1 CONNECTORS, TOUSCHSCREEN
- CSI / LVDS Routing
- CSI1 / DISP1 Connector
- VID_IN_CSI1_HSYNC
- VID_IN_CSI1_VSYNC
- VID_IN_CSI1_PIXCLK
- DISP1_PIXCLK
- DISP1_HSYNC
- DISP1_VSYNC
- *0
- VID_IN_CSI1_D0
- VID_IN_CSI1_D1
- VID_IN_CSI1_D2
- VID_IN_CSI1_D3
- DISP1_D0
- DISP1_D1
- DISP1_D2
- DISP1_D3
- DESIGN NOTE:
  Fit only one resistor per one signal according to the picture below.
- VID_IN_CSI1_D4
- VID_IN_CSI1_D5
- VID_IN_CSI1_D6
- VID_IN_CSI1_D7
- DISP1_D4
- DISP1_D5
- DISP1_D6
- DISP1_D7
- CPU CSI
- CON
- CPU LVDS
- VID_IN_CSI1_D8
- VID_IN_CSI1_D9
- VID_IN_CSI1_D10
- VID_IN_CSI1_D11
- DISP1_D8
- DISP1_D9
- DISP1_D10
- DISP1_D11
- *1
- LVDS to CON
- 0R
- VID_IN_CSI1_D12
- VID_IN_CSI1_D13
- VID_IN_CSI1_D14
- VID_IN_CSI1_D15
- DISP1_D12
- DISP1_D13
- DISP1_D14
- DISP1_D15
- CSI to CON
- VID_IN_CSI1_D16
- VID_IN_CSI1_D17
- VID_IN_CSI1_D18
- VID_IN_CSI1_D19
- DISP1_D16
- DISP1_D17
- DISP1_D18
- DISP1_D19
- VID_IN_CSI1_RSTn
- VID_IN_CSI1_INT
- VID_IN_CSI1_DE
- VID_IN_CSI1_INT2
- DISP1_RSTn
- DISP1_RDX
- DISP1_WRX
- DISP1_CS0
- DESIGN NOTE:
  Be aware, after reset some CSI1 / DISP1 pins are set as output. Be sure before you enable a camera, these pins should be set correctly as inputs otherwise there may be a conflict between camera and CPU pins.
  Default state of CSI1/DISP1 signal after reset:
  *0 - Ouptut Low
  *1 - Output High
- DESIGN NOTE:
  Contacts are located on the top side of the pins of FFC connector.
- CSI Camera / LVDS Connector
- Touchscreen Connector
- (Raspberry Pi compatible)
- LVDS0_TX0_R_N
- LVDS0_TX1_R_N
- LVDS0_TX0_R_P
- LVDS0_TX1_R_P
- CSI_GPIO1_R
- CSI_GPIO0_R
- LVDS0_TX2_R_P
- LVDS0_TX2_R_N
- DESIGN NOTE:
  Before you plug in cable into connector J12, be sure, that the correct interface is selected with the optional series resistors.
- LVDS0_DPS
- LVDS0_FRC
- DESIGN NOTE:
  CSI connector is pin compatable with Raspbery Pi camera connector.
- DESIGN NOTE:
  Touchscreen is connected to MCU LPC13xx. These signals can be configured also as Analog inputs, GPIO or PWM outputs.
- FREE for personal and commercial use. See the license.
- DESIGN NOTE:
  FRC - number of colors used:
  High: 16,777,216 colors
  Low or Open: 262,144 colors
- DESIGN NOTE:
  DPS -  scan direction:
  High: Reverse scan
  Low or Open: Normal scan
- DESIGN NOTE:
  If FRC & DPS are used (for some LVDS displays), do not fit R154 & R156 and choose the proper combination of resistors R52, R53, R54 & R191.
- Variant:
- Checked by
- Designed by www.fedevel.com

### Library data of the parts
C225 C278 = C1608X5R0J106M: CAP CER 10UF 6.3V X5R 20% 0603; Manufacturer: TDK Corporation; Capacitance: 10µF; Value: 10µF; .Checked PCB: used
C226 C279 = C1005X5R1H104K: CAP CER .10UF 50V X5R 10% 0402; Manufacturer: TDK Corporation; Capacitance: 0.1µF; Value: 100nF; .Checked PCB: used
D37 = BZA956A,115: TVS ZENER QUAD 5.6V SOT665; Manufacturer: NXP Semiconductors; Voltage - Reverse Standoff (Typ): 3V; Voltage - Breakdown: 5.32V; Power (Watts): 16W; Polarization: 4 Channel Array - Unidirectional; .Creator: MM; .Checked PCB: used
FB14 FB16 = BLM18SG221TN1D: FERRITE CHIP 220 OHM 2500MA 0603; Manufacturer: Murata Electronics North America; Impedance @ Frequency: 220 Ohm @ 100MHz; DC Resistance (DCR): 40 mOhm Max; Filter Type: Differential Mode - Single; Number of Lines: 1; .Checked PCB: used
J7 = 4-1734592-0: CONN FPC BOTTOM 40POS 0.50MM R/A; Manufacturer: TE Connectivity; Connector/Contact Type: Contacts, Bottom; Number of Positions: 40; Pitch: 0.020" (0.50mm); FFC, FCB Thickness: 0.30mm; Locking Feature: Slide Lock; Cable End Type: Tapered; Actuator Material: Thermoplastic; Voltage Rating: 250V; Material Flammability Rating: UL94 V-0; Current Rating: 0.5A; .Creator: MM
J10 = 0532610471: CONN HEADER 4POS 1.25MM R/A SMD; Manufacturer: Molex Inc; Connector Type: Header, Shrouded; Number of Positions: 4; Number of Positions Loaded: All; Pitch: 0.049" (1.25mm); .Creator: MM; .Checked PCB: used
J12 = 1-84952-5: CONN FPC BOTTOM 15POS 1.00MM R/A; Manufacturer: TE Connectivity; Connector/Contact Type: Contacts, Bottom; Number of Positions: 15; Pitch: 0.039" (1.00mm); FFC, FCB Thickness: 0.30mm; Locking Feature: Slide Lock; Cable End Type: Straight; Actuator Material: Polyamide (PA), Nylon, Glass Filled; Voltage Rating: 200V; Material Flammability Rating: UL94 V-0; Current Rating: 1A; .Creator: MM
R33 R65 R71 R119-R123 R125-R129 R135 R136 R138 R154 R156 R195 R196 = RC0402JR-070RL: RES 0.0 OHM 1/16W 0402 SMD; Manufacturer: Yageo; Resistance (Ohms): 0.0; Power (Watts): 0.063W, 1/16W; Tolerance: Jumper; .Checked PCB: used
R52-R54 R191 = RC0402FR-0710KL: RES 10.0K OHM 1/16W 1% 0402 SMD; Manufacturer: Yageo; Power (Watts): 0.063W, 1/16W; .Checked PCB: used; Temperature Coefficient: ±100ppm/°C
R275 = RC0402FR-0722RL: RES 22.0 OHM 1/16W 1% 0402 SMD; Manufacturer: Yageo; Resistance (Ohms): 22; Power (Watts): 0.063W, 1/16W; .Checked PCB: used; Temperature Coefficient: ±100ppm/°C
TP19 TP20 = TP_25MILC: Test Point 25mil

## Sheet [04] - CPU - PCIE, USB.SchDoc
size A2; DocumentNumber: 4; SheetNumber: 4; SheetTotal: 31
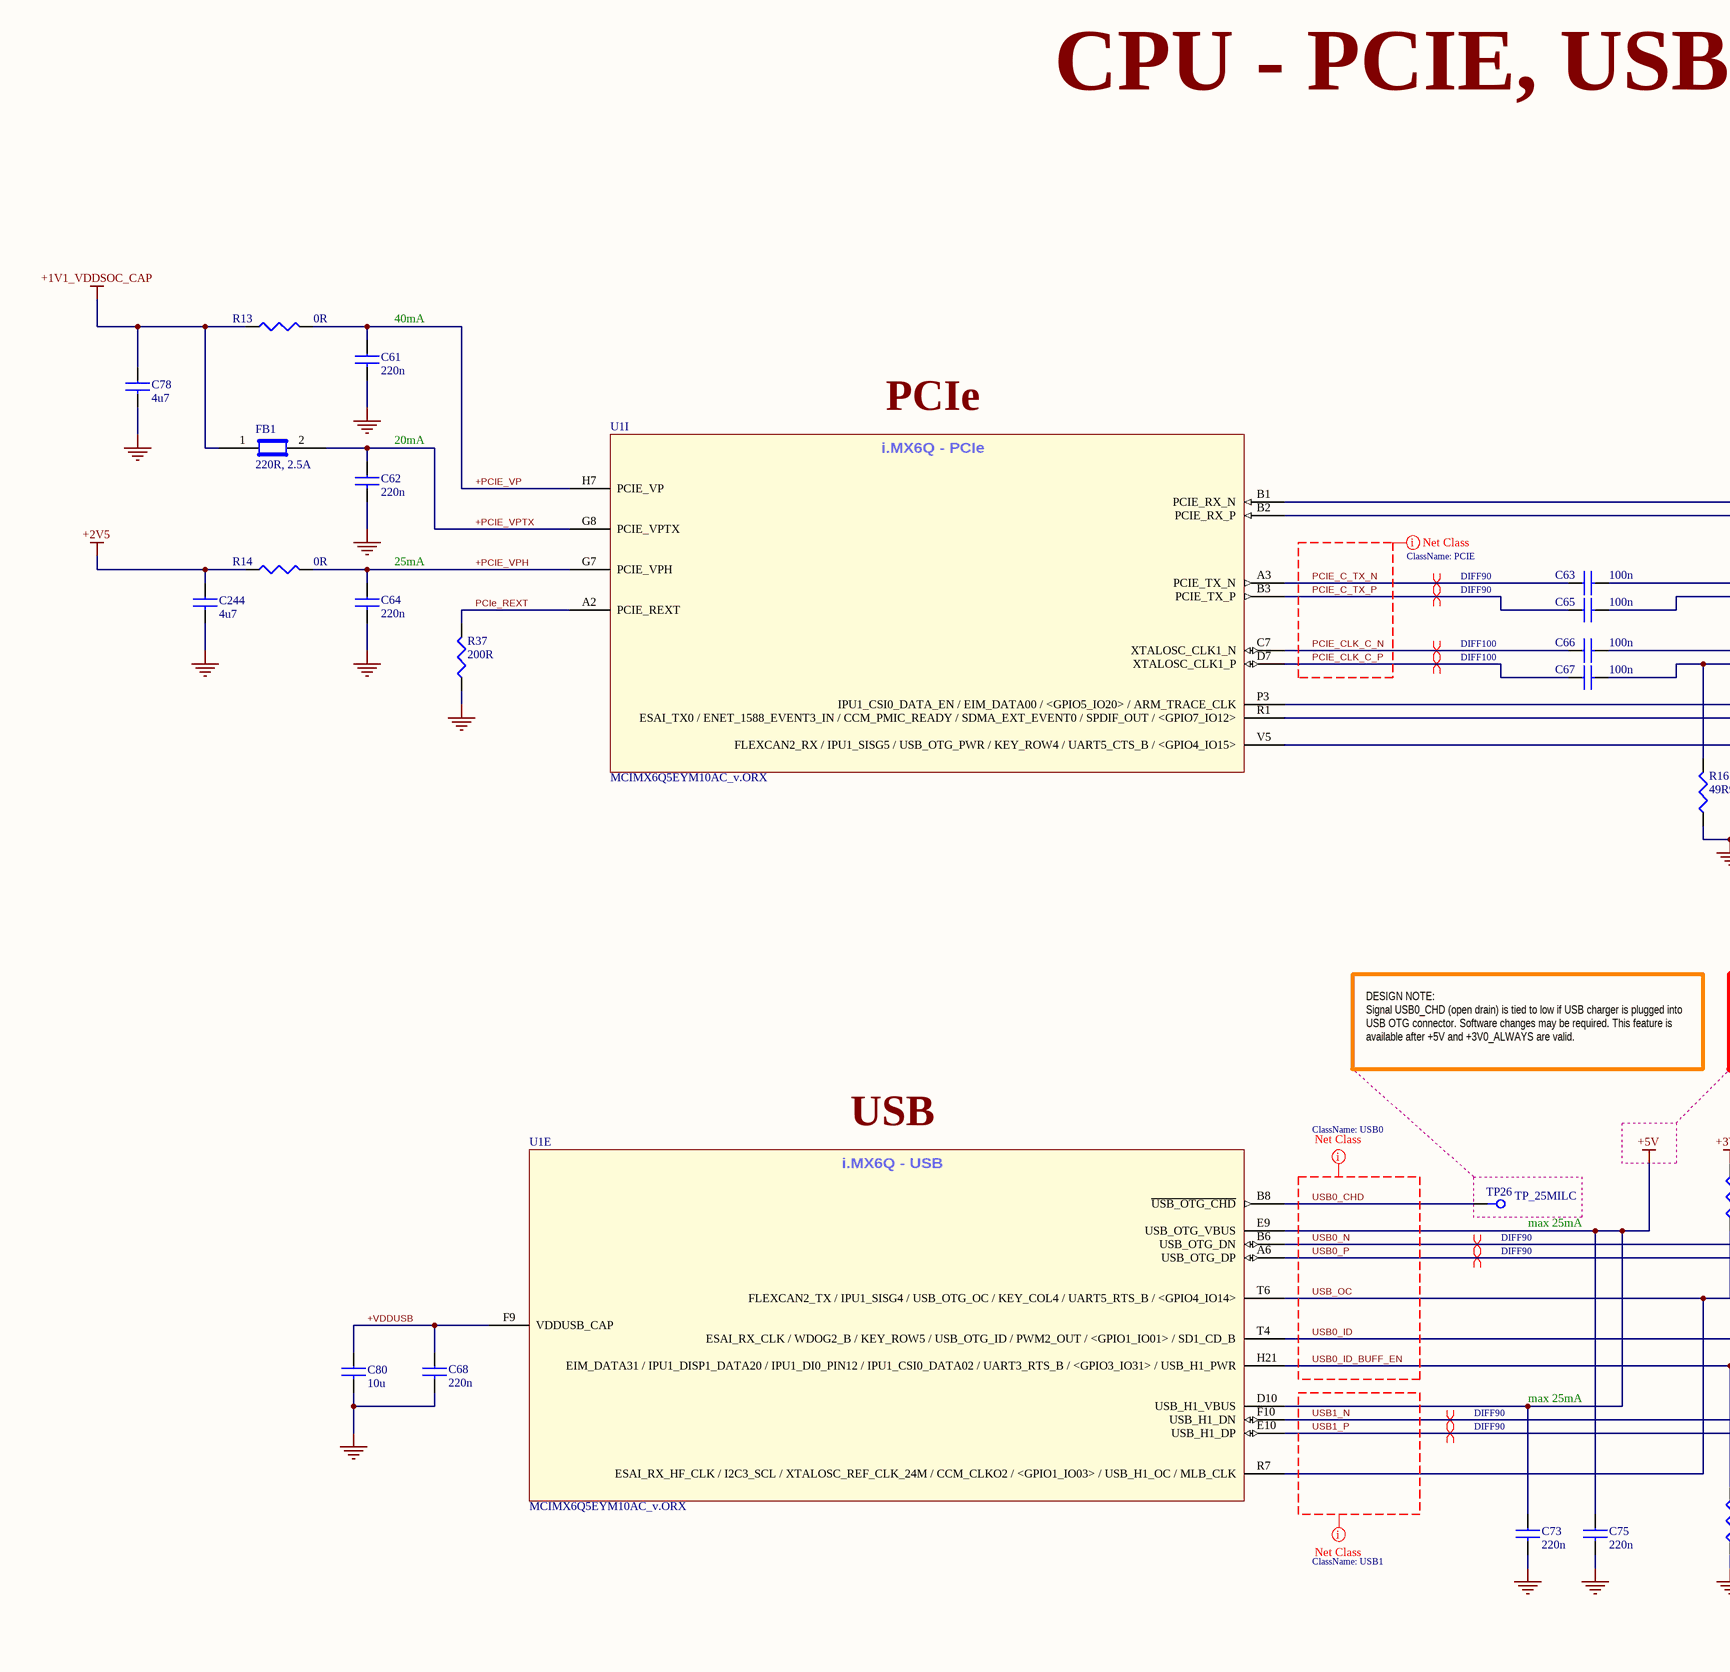
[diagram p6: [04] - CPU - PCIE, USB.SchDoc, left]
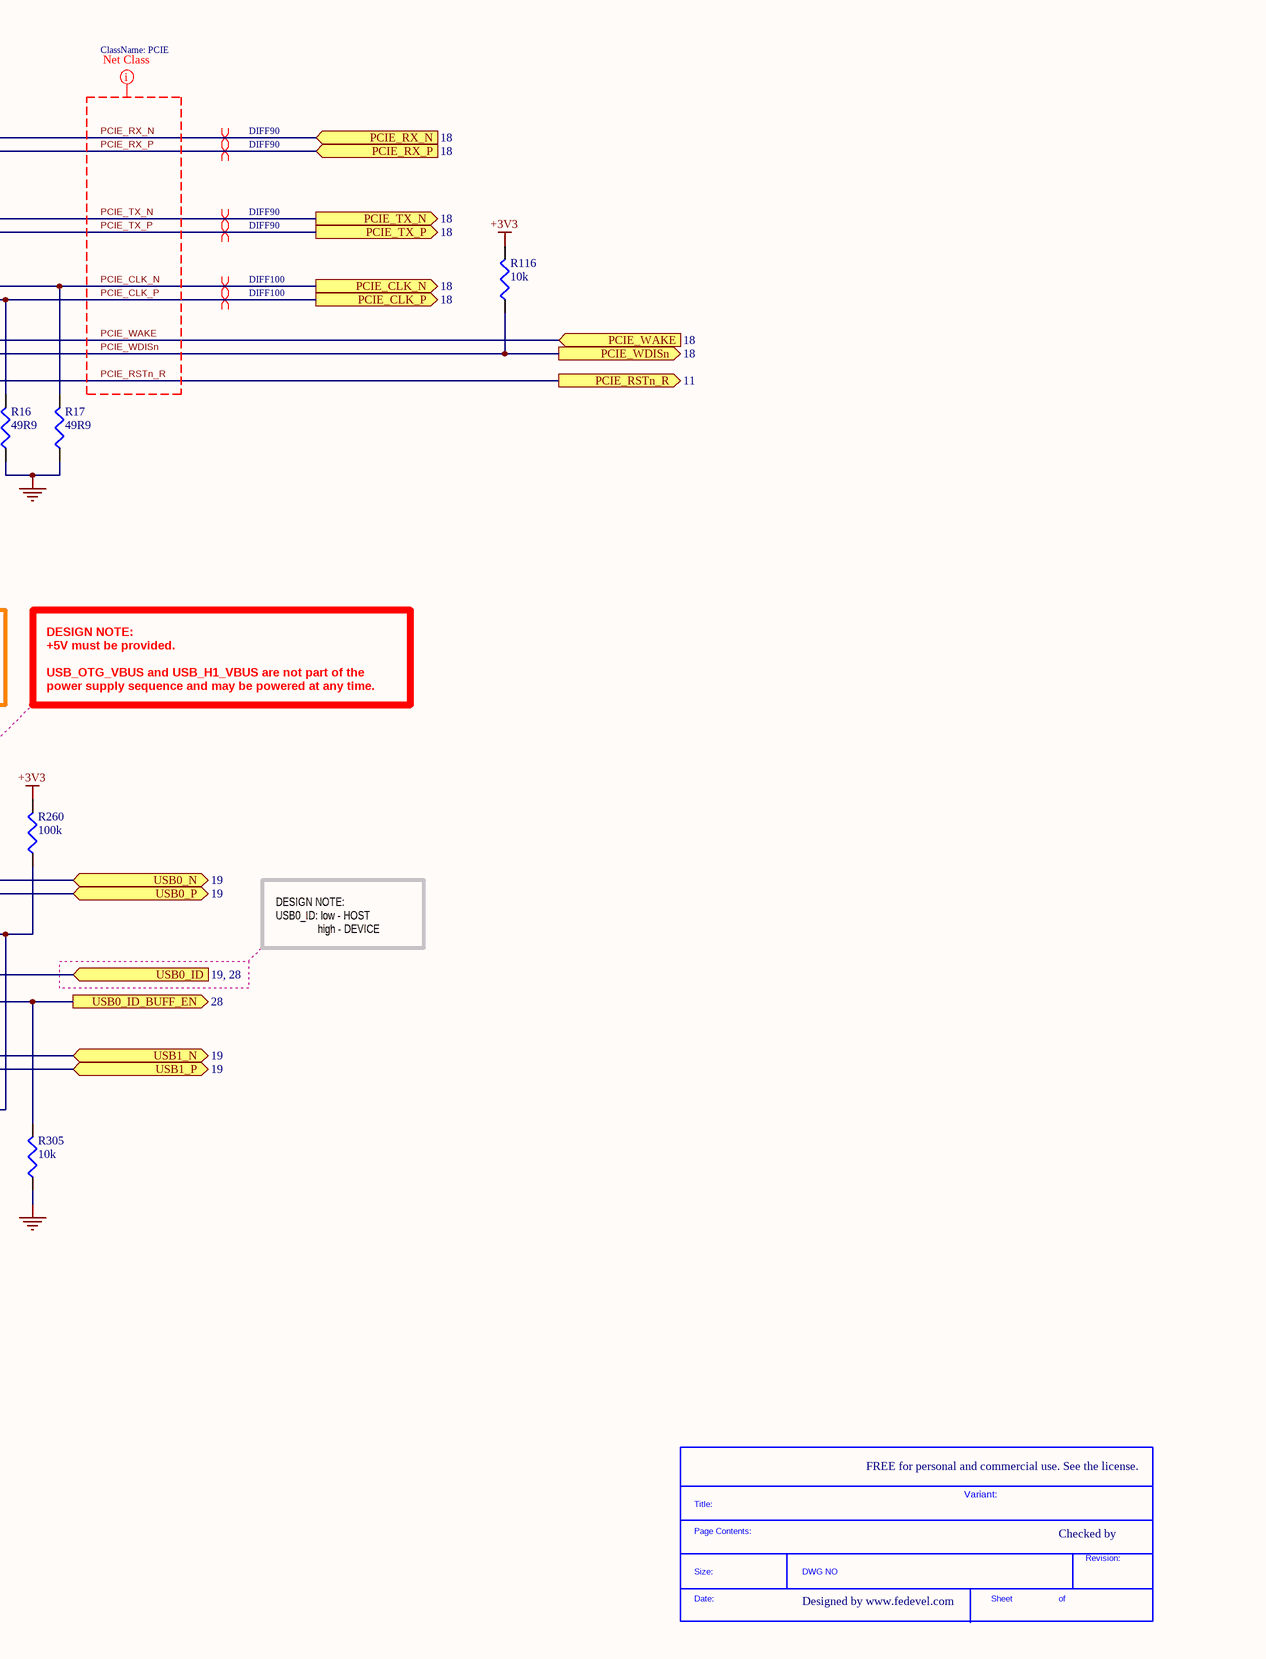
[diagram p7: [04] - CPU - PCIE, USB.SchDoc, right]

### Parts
(Parts that share a designator on the sheet are numbered #1, #2 ... from top to bottom, then left to right.)
*#5  SDTitleBlock  (value not drawn)  (graphical)
C61  220n  [C0201]
C62  220n  [C0201]
C63  100n  [C0402]
C64  220n  [C0201]
C65  100n  [C0402]
C66  100n  [C0402]
C67  100n  [C0402]
C68  220n  [C0201]
C73  220n  [C0201]
C75  220n  [C0201]
C78  4u7  [C0402]
C80  10u  [C0603]
C244  4u7  [C0402]
FB1  220R, 2.5A  [C0603]
R13  0R  [R0402]
R14  0R  [R0402]
R16  49R9  [R0402]
R17  49R9  [R0402]
R37  200R  [R0402]
R116  10k  [R0402]
R260  100k  [R0201]
R305  10k  [R0402]
TP26  TP_25MILC  [TP_25C]  (no BOM)
U1  MCIMX6Q5EYM10AC_v.ORX  [PBGA624]  (parts E,I of 21)

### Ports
PCIE_CLK_N (out, see 18), PCIE_CLK_P (out, see 18), PCIE_RSTn_R (out, see 11), PCIE_RX_N (in, see 18), PCIE_RX_P (in, see 18), PCIE_TX_N (out, see 18), PCIE_TX_P (out, see 18), PCIE_WAKE (in, see 18), PCIE_WDISn (out, see 18), USB0_ID (see 19, 28), USB0_ID_BUFF_EN (out, see 28), USB0_N (bidir, see 19), USB0_P (bidir, see 19), USB1_N (bidir, see 19), USB1_P (bidir, see 19)

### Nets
+1V1_VDDSOC_CAP: C78.1 FB1.1 R13.1
+2V5: C244.1 R14.1
+3V3: R116.2 R260.2
+5V: C73.1 C75.1 U1.D10(USB_H1_VBUS) U1.E9(USB_OTG_VBUS)
GND: C61.2 C62.2 C64.2 C68.2 C73.2 C75.2 C78.2 C80.2 C244.2 R16.1 R17.1 R37.1 R305.1
+PCIE_VP: C61.1 R13.2 U1.H7(PCIE_VP)
+PCIE_VPH: C64.1 R14.2 U1.G7(PCIE_VPH)
+PCIE_VPTX: C62.1 FB1.2 U1.G8(PCIE_VPTX)
+VDDUSB: C68.1 C80.1 U1.F9(VDDUSB_CAP)
PCIE_C_TX_N: C63.1 U1.A3(PCIE_TX_N)
PCIE_C_TX_P: C65.1 U1.B3(PCIE_TX_P)
PCIE_CLK_C_N: C66.1 U1.C7(XTALOSC_CLK1_N)
PCIE_CLK_C_P: C67.1 U1.D7(XTALOSC_CLK1_P)
PCIE_CLK_N: C66.2 R17.2 ; port PCIE_CLK_N
PCIE_CLK_P: C67.2 R16.2 ; port PCIE_CLK_P
PCIe_REXT: R37.2 U1.A2(PCIE_REXT)
PCIE_RSTn_R: U1.V5(FLEXCAN2_RX_/_IPU1_SISG5_/_USB_OTG_PWR_/_KEY_ROW4_/_UART5_CTS_B_/_<GPIO4_IO15>) ; port PCIE_RSTn_R
PCIE_RX_N: U1.B1(PCIE_RX_N) ; port PCIE_RX_N
PCIE_RX_P: U1.B2(PCIE_RX_P) ; port PCIE_RX_P
PCIE_TX_N: C63.2 ; port PCIE_TX_N
PCIE_TX_P: C65.2 ; port PCIE_TX_P
PCIE_WAKE: U1.P3(IPU1_CSI0_DATA_EN_/_EIM_DATA00_/_<GPIO5_IO20>_/_ARM_TRACE_CLK) ; port PCIE_WAKE
PCIE_WDISn: R116.1 U1.R1(ESAI_TX0_/_ENET_1588_EVENT3_IN_/_CCM_PMIC_READY_/_SDMA_EXT_EVENT0_/_SPDIF_OUT_/_<GPIO7_IO12>) ; port PCIE_WDISn
USB0_CHD: TP26.1 U1.B8(~{USB_OTG_CHD})
USB0_ID: U1.T4(ESAI_RX_CLK_/_WDOG2_B_/_KEY_ROW5_/_USB_OTG_ID_/_PWM2_OUT_/_<GPIO1_IO01>_/_SD1_CD_B) ; port USB0_ID
USB0_ID_BUFF_EN: R305.2 U1.H21(EIM_DATA31_/_IPU1_DISP1_DATA20_/_IPU1_DI0_PIN12_/_IPU1_CSI0_DATA02_/_UART3_RTS_B_/_<GPIO3_IO31>_/_USB_H1_PWR) ; port USB0_ID_BUFF_EN
USB0_N: U1.B6(USB_OTG_DN) ; port USB0_N
USB0_P: U1.A6(USB_OTG_DP) ; port USB0_P
USB1_N: U1.F10(USB_H1_DN) ; port USB1_N
USB1_P: U1.E10(USB_H1_DP) ; port USB1_P
USB_OC: R260.1 U1.R7(ESAI_RX_HF_CLK_/_I2C3_SCL_/_XTALOSC_REF_CLK_24M_/_CCM_CLKO2_/_<GPIO1_IO03>_/_USB_H1_OC_/_MLB_CLK) U1.T6(FLEXCAN2_TX_/_IPU1_SISG4_/_USB_OTG_OC_/_KEY_COL4_/_UART5_RTS_B_/_<GPIO4_IO14>)

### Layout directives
differential pair; net class DIFF100: PCIE_CLK_C_N, PCIE_CLK_C_P, PCIE_CLK_N, PCIE_CLK_P
differential pair; net class DIFF90: PCIE_C_TX_N, PCIE_C_TX_P, PCIE_RX_N, PCIE_RX_P, PCIE_TX_N, PCIE_TX_P, USB0_N, USB0_P, USB1_N, USB1_P
net class PCIE: PCIE_C_TX_N, PCIE_C_TX_P, PCIE_CLK_C_N, PCIE_CLK_C_P, PCIE_CLK_N, PCIE_CLK_P, PCIE_RSTn_R, PCIE_RX_N, PCIE_RX_P, PCIE_TX_N, PCIE_TX_P, PCIE_WAKE, PCIE_WDISn
net class USB0: USB0_CHD, USB0_ID, USB0_ID_BUFF_EN, USB0_N, USB0_P, USB_OC
net class USB1: USB1_N, USB1_P

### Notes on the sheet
- CPU - PCIE, USB
- (near C61) 40mA
- PCIe
- (near C62) 20mA
- (near C64) 25mA
- DESIGN NOTE:
  Signal USB0_CHD (open drain) is tied to low if USB charger is plugged into USB OTG connector. Software changes may be required. This feature is available after +5V and +3V0_ALWAYS are valid.
- DESIGN NOTE:
  +5V must be provided.
  USB_OTG_VBUS and USB_H1_VBUS are not part of the power supply sequence and may be powered at any time.
- USB
- (near TP26) max 25mA
- DESIGN NOTE:
  USB0_ID: low - HOST
  high - DEVICE
- max 25mA
- FREE for personal and commercial use. See the license.
- Variant:
- Checked by
- Designed by www.fedevel.com

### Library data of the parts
C61 C62 C64 C68 C73 C75 = C0603X5R0J224M030BB: CAP CER 0.22UF 6.3V 20% X5R 0201; Manufacturer: TDK Corporation; Capacitance: 0.22µF; .Checked PCB: MM
C63 C65-C67 = C1005X5R1H104K: as C226 on sheet [17] - LVDS, CSI, LCD, TSC
C78 C244 = C1005X5R1A475M: CAP CER 4.7UF 10V 20% X5R 0402; Manufacturer: TDK Corporation; Capacitance: 4.7µF; .Checked PCB: used
C80 = C1608X5R0J106M: as C225 on sheet [17] - LVDS, CSI, LCD, TSC
FB1 = BLM18SG221TN1D: as FB14 on sheet [17] - LVDS, CSI, LCD, TSC
R13 R14 = RC0402JR-070RL: as R33 on sheet [17] - LVDS, CSI, LCD, TSC
R16 R17 = RC0402FR-0749R9L: RES 49.9 OHM 1/16W 1% 0402 SMD; Manufacturer: Yageo; Resistance (Ohms): 49.9; Power (Watts): 0.063W, 1/16W; Value: 49.9R; .Checked PCB: used; Temperature Coefficient: ±100ppm/°C
R37 = CRCW0402200RFKED: RES 200 OHM 1/16W 1% 0402 SMD; Manufacturer: Vishay Dale; Resistance (Ohms): 200; Power (Watts): 0.063W, 1/16W; Temperature Coefficient: ±100ppm/°C; .Checked PCB: used; .Creator: MM
R116 R305 = RC0402FR-0710KL: as R52 on sheet [17] - LVDS, CSI, LCD, TSC
R260 = RC0201FR-07100KL: RES 100K OHM 1/20W 1% 0201 SMD; Manufacturer: Yageo; Power (Watts): 0.05W, 1/20W; Temperature Coefficient: ±200ppm/°C; .Creator: MM
TP26 = TP_25MILC: Test Point 25mil
U1 = MCIMX6Q5EYM10AC_v.ORX: IC MCU 32BIT ARM QUAD 624FCBGA; Manufacturer: Freescale Semiconductor; Speed: 1.0GHz; .Creator: MM; .Checked PCB: MM, checked by RF; Core Processor: ARM® Cortex™-A9; Core Size: 32-Bit Quad-Core; Connectivity: CAN, EBI/EMI, ESAI, Ethernet, GPMI, I2C, MMC/SD, PCI, SATA, SPI, UART, USB, USB OTG; Peripherals: DMA, HDMI, I2S/SSI/AC97, MIPI CSI, MIMI DSI, MIPI HIS, PWM, WDT; Number of I /O: 224; Program Memory Type: External Program Memory; RAM Size: 256K x 8; Voltage - Supply (Vcc/Vdd): 0.925 V ~ 1.5 V; Oscillator Type: Internal

## Sheet [05] - CPU - HDMI, LVDS.SchDoc
size A2; DocumentNumber: 5; SheetNumber: 5; SheetTotal: 31
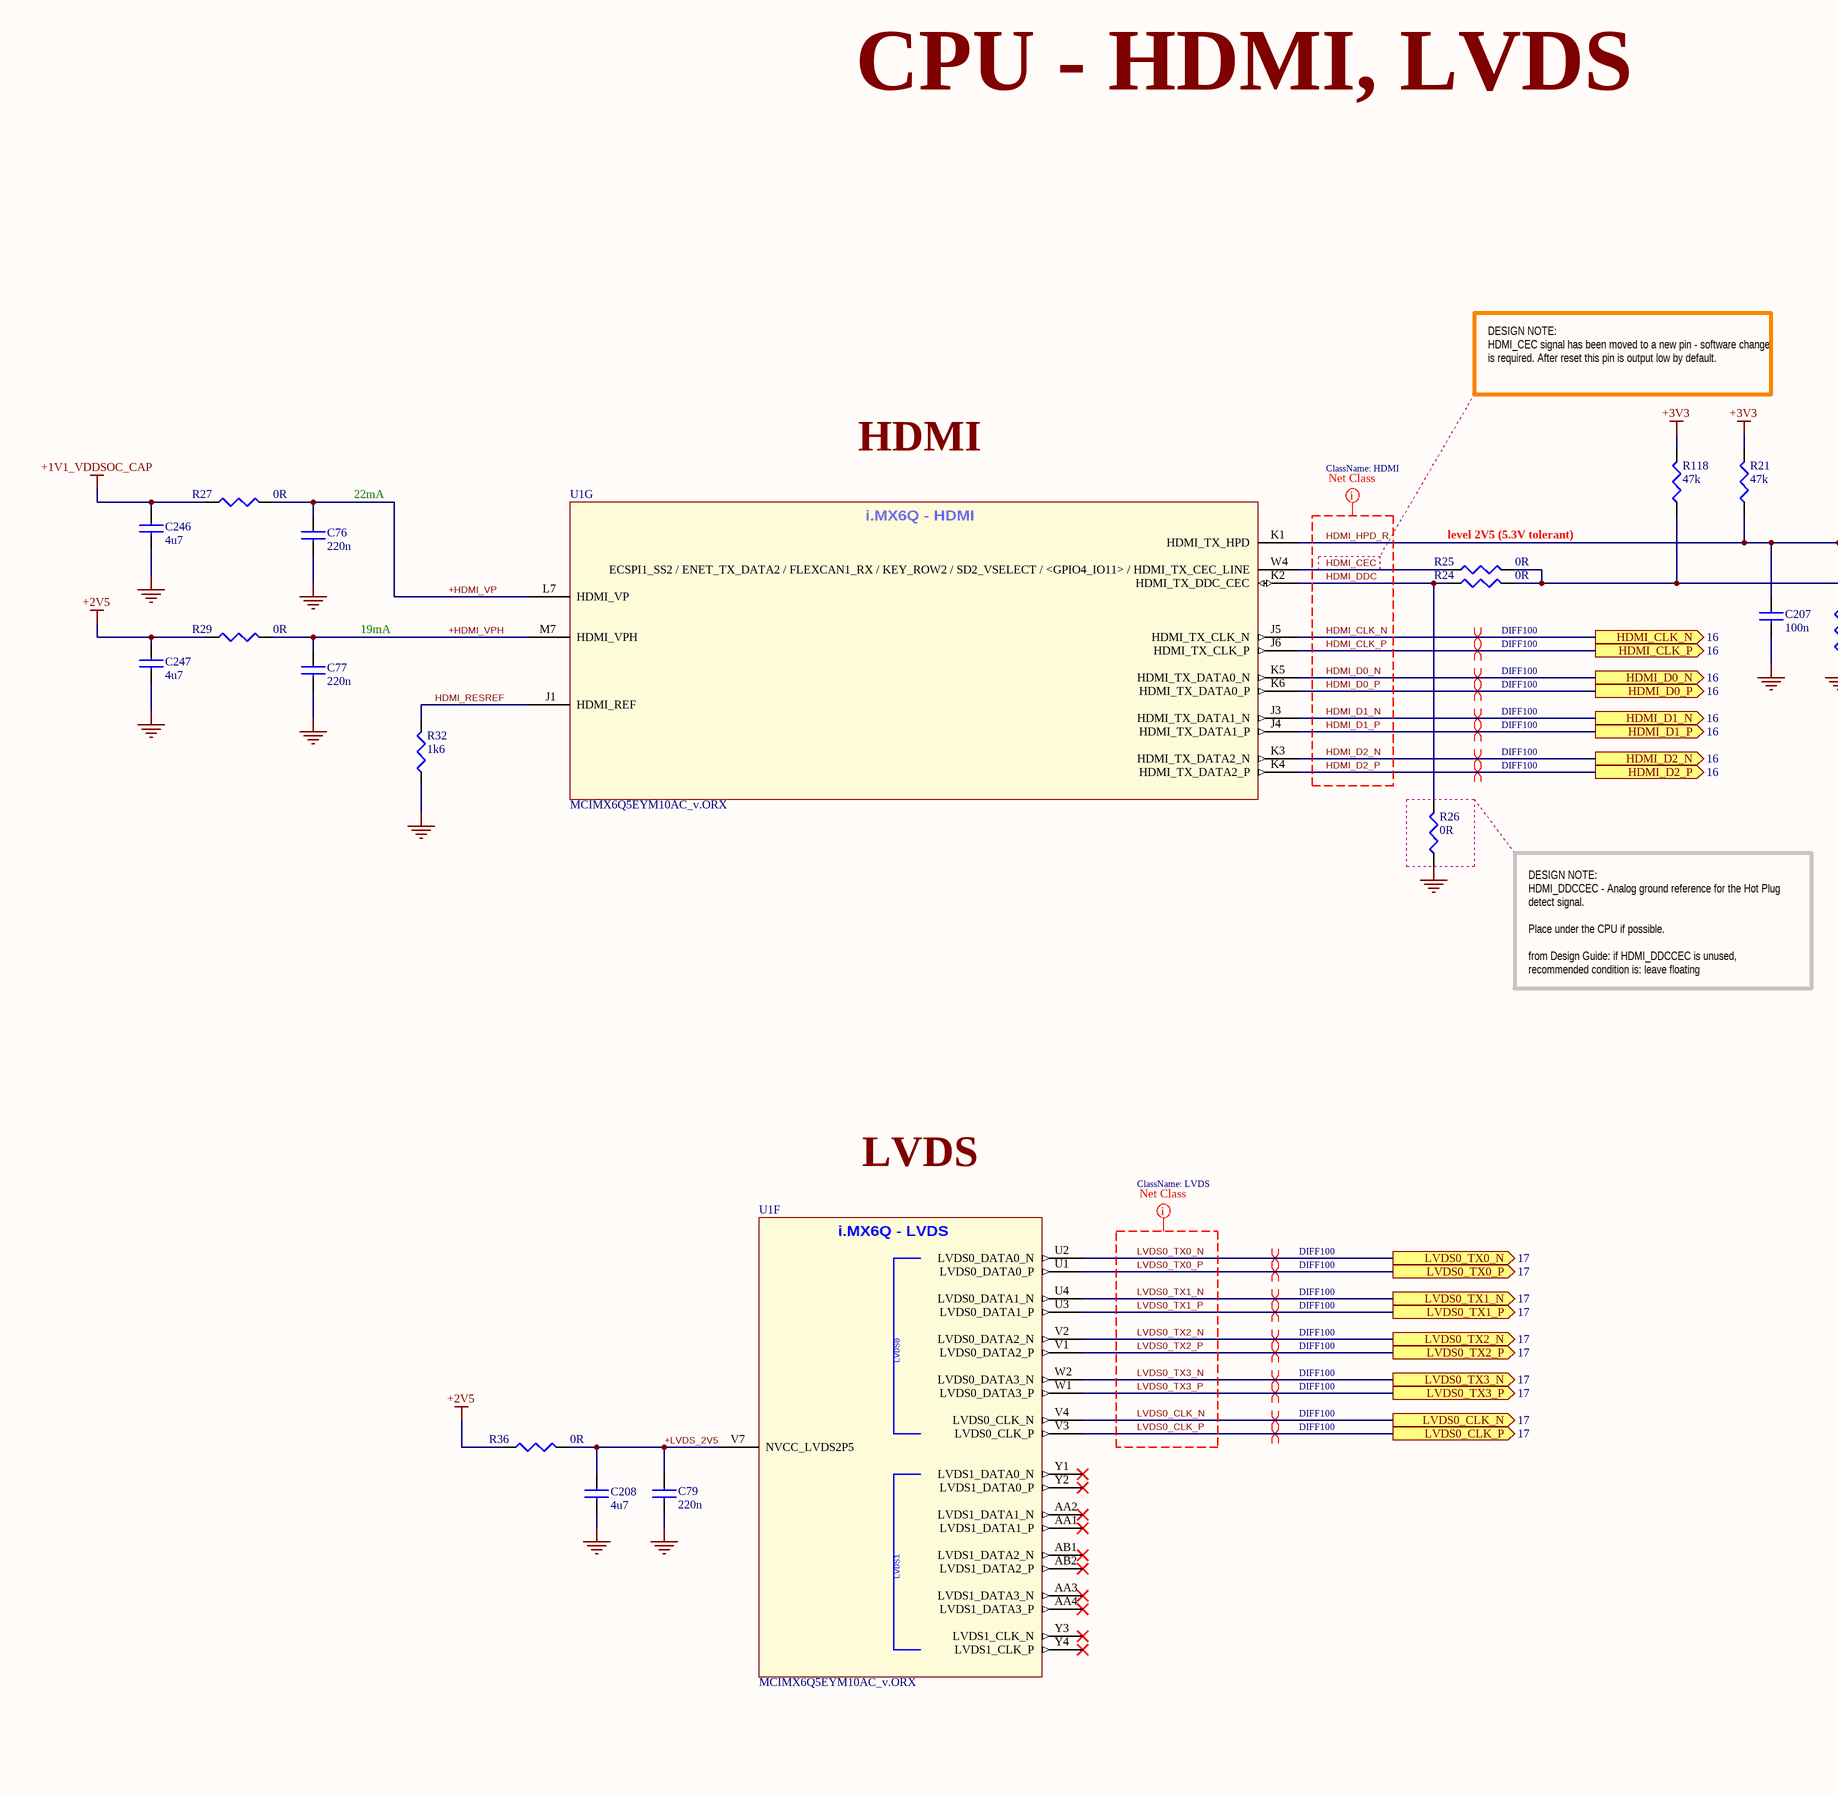
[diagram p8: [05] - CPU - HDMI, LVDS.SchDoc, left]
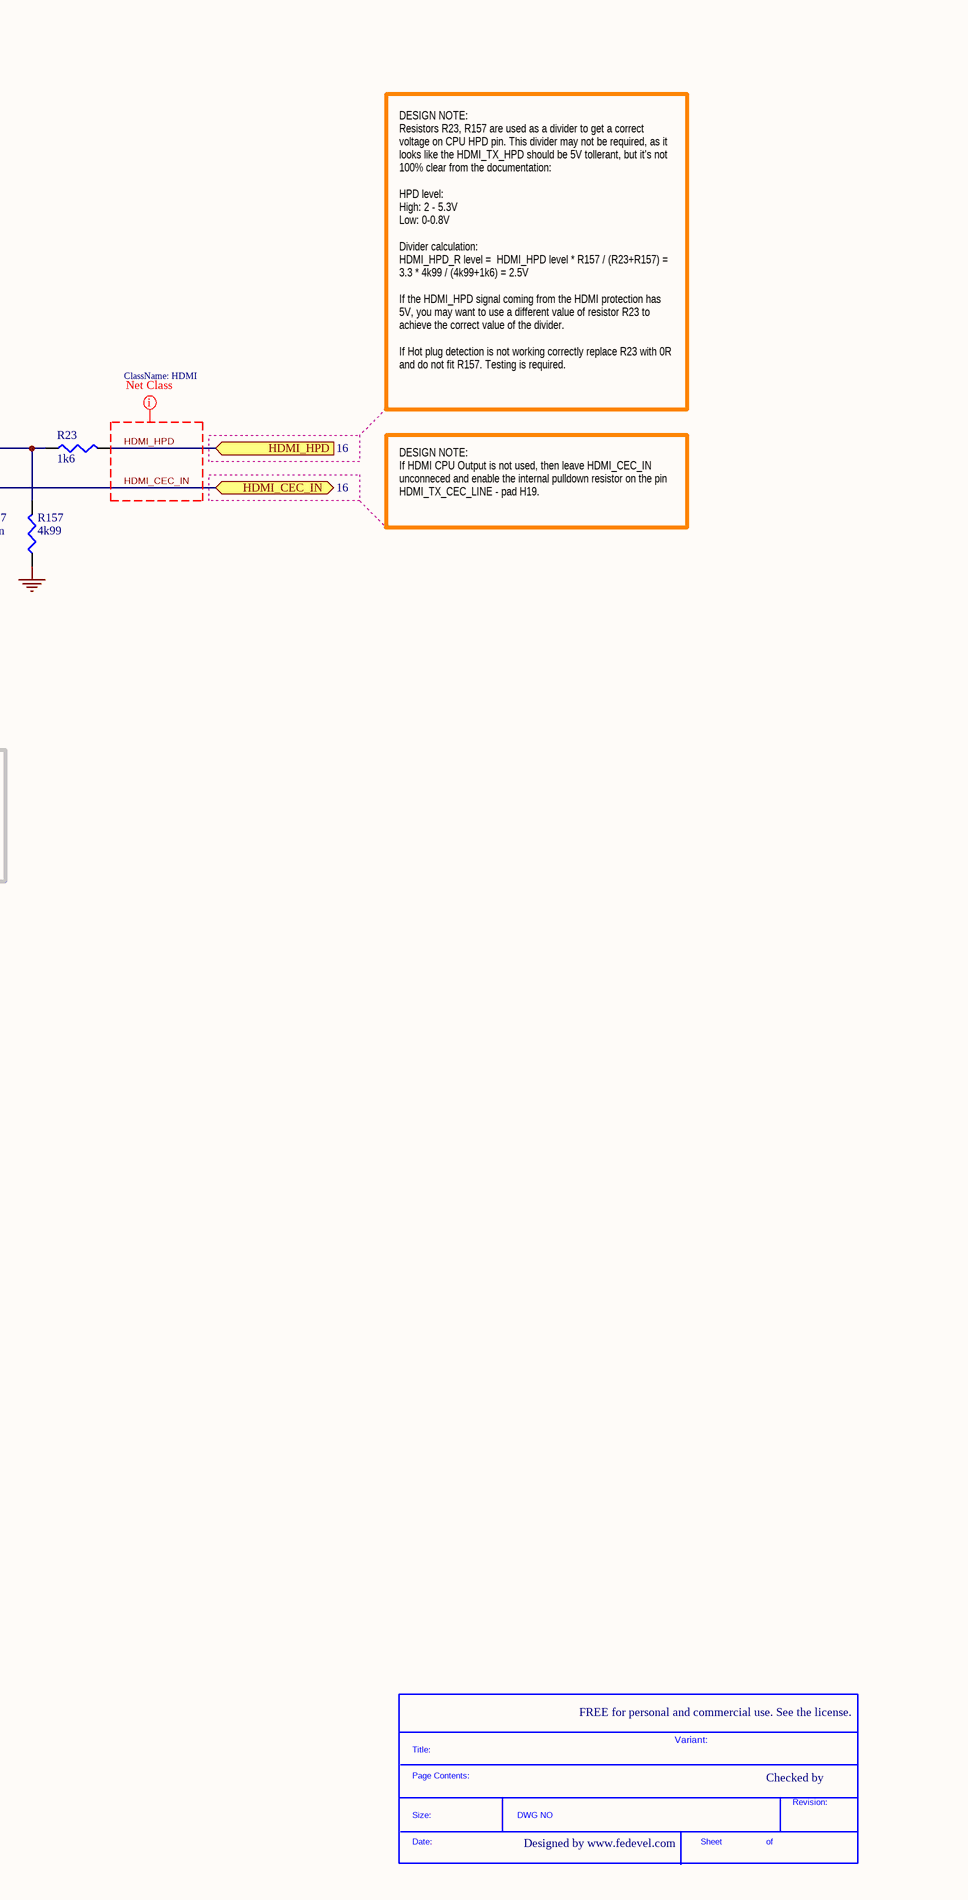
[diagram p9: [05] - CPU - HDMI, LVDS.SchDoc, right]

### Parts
(Parts that share a designator on the sheet are numbered #1, #2 ... from top to bottom, then left to right.)
*#6  SDTitleBlock  (value not drawn)  (graphical)
C76  220n  [C0201]
C77  220n  [C0201]
C79  220n  [C0201]
C207  100n  [C0402]
C208  4u7  [C0402]
C246  4u7  [C0402]
C247  4u7  [C0402]
R21  47k  [R0402]
R23  1k6  [R0402]
R24  0R  [R0402]
R25  0R  [R0402]
R26  0R  [R0402]
R27  0R  [R0402]
R29  0R  [R0402]
R32  1k6  [R0201]
R36  0R  [R0402]
R118  47k  [R0402]
R157  4k99  [R0402]
U1  MCIMX6Q5EYM10AC_v.ORX  [PBGA624]  (parts F,G of 21)

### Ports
HDMI_CEC_IN (bidir, see 16), HDMI_CLK_N (out, see 16), HDMI_CLK_P (out, see 16), HDMI_D0_N (out, see 16), HDMI_D0_P (out, see 16), HDMI_D1_N (out, see 16), HDMI_D1_P (out, see 16), HDMI_D2_N (out, see 16), HDMI_D2_P (out, see 16), HDMI_HPD (in, see 16), LVDS0_CLK_N (out, see 17), LVDS0_CLK_P (out, see 17), LVDS0_TX0_N (out, see 17), LVDS0_TX0_P (out, see 17), LVDS0_TX1_N (out, see 17), LVDS0_TX1_P (out, see 17), LVDS0_TX2_N (out, see 17), LVDS0_TX2_P (out, see 17), LVDS0_TX3_N (out, see 17), LVDS0_TX3_P (out, see 17)

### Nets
+1V1_VDDSOC_CAP: C246.1 R27.1
+2V5: C247.1 R29.1 R36.1
+3V3: R21.2 R118.2
GND: C76.2 C77.2 C79.2 C207.2 C208.2 C246.2 C247.2 R26.1 R32.1 R157.1
+HDMI_VP: C76.1 R27.2 U1.L7(HDMI_VP)
+HDMI_VPH: C77.1 R29.2 U1.M7(HDMI_VPH)
+LVDS_2V5: C79.1 C208.1 R36.2 U1.V7(NVCC_LVDS2P5)
HDMI_CEC: R25.1 U1.W4(ECSPI1_SS2_/_ENET_TX_DATA2_/_FLEXCAN1_RX_/_KEY_ROW2_/_SD2_VSELECT_/_<GPIO4_IO11>_/_HDMI_TX_CEC_LINE)
HDMI_CEC_IN: R24.2 R25.2 R118.1 ; port HDMI_CEC_IN
HDMI_CLK_N: U1.J5(HDMI_TX_CLK_N) ; port HDMI_CLK_N
HDMI_CLK_P: U1.J6(HDMI_TX_CLK_P) ; port HDMI_CLK_P
HDMI_D0_N: U1.K5(HDMI_TX_DATA0_N) ; port HDMI_D0_N
HDMI_D0_P: U1.K6(HDMI_TX_DATA0_P) ; port HDMI_D0_P
HDMI_D1_N: U1.J3(HDMI_TX_DATA1_N) ; port HDMI_D1_N
HDMI_D1_P: U1.J4(HDMI_TX_DATA1_P) ; port HDMI_D1_P
HDMI_D2_N: U1.K3(HDMI_TX_DATA2_N) ; port HDMI_D2_N
HDMI_D2_P: U1.K4(HDMI_TX_DATA2_P) ; port HDMI_D2_P
HDMI_DDC: R24.1 R26.2 U1.K2(HDMI_TX_DDC_CEC)
HDMI_HPD: R23.2 ; port HDMI_HPD
HDMI_HPD_R: C207.1 R21.1 R23.1 R157.2 U1.K1(HDMI_TX_HPD)
HDMI_RESREF: R32.2 U1.J1(HDMI_REF)
LVDS0_CLK_N: U1.V4(LVDS0_CLK_N) ; port LVDS0_CLK_N
LVDS0_CLK_P: U1.V3(LVDS0_CLK_P) ; port LVDS0_CLK_P
LVDS0_TX0_N: U1.U2(LVDS0_DATA0_N) ; port LVDS0_TX0_N
LVDS0_TX0_P: U1.U1(LVDS0_DATA0_P) ; port LVDS0_TX0_P
LVDS0_TX1_N: U1.U4(LVDS0_DATA1_N) ; port LVDS0_TX1_N
LVDS0_TX1_P: U1.U3(LVDS0_DATA1_P) ; port LVDS0_TX1_P
LVDS0_TX2_N: U1.V2(LVDS0_DATA2_N) ; port LVDS0_TX2_N
LVDS0_TX2_P: U1.V1(LVDS0_DATA2_P) ; port LVDS0_TX2_P
LVDS0_TX3_N: U1.W2(LVDS0_DATA3_N) ; port LVDS0_TX3_N
LVDS0_TX3_P: U1.W1(LVDS0_DATA3_P) ; port LVDS0_TX3_P

Not connected (* = marked no-connect by the designer): U1 AA1(LVDS1_DATA1_P)* AA2(LVDS1_DATA1_N)* AA3(LVDS1_DATA3_N)* AA4(LVDS1_DATA3_P)* AB1(LVDS1_DATA2_N)* AB2(LVDS1_DATA2_P)* Y1(LVDS1_DATA0_N)* Y2(LVDS1_DATA0_P)* Y3(LVDS1_CLK_N)* Y4(LVDS1_CLK_P)*

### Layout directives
differential pair; net class DIFF100: HDMI_CLK_N, HDMI_CLK_P, HDMI_D0_N, HDMI_D0_P, HDMI_D1_N, HDMI_D1_P, HDMI_D2_N, HDMI_D2_P, LVDS0_CLK_N, LVDS0_CLK_P, LVDS0_TX0_N, LVDS0_TX0_P, LVDS0_TX1_N, LVDS0_TX1_P, LVDS0_TX2_N, LVDS0_TX2_P, LVDS0_TX3_N, LVDS0_TX3_P
net class HDMI: HDMI_CEC, HDMI_CEC_IN, HDMI_CLK_N, HDMI_CLK_P, HDMI_D0_N, HDMI_D0_P, HDMI_D1_N, HDMI_D1_P, HDMI_D2_N, HDMI_D2_P, HDMI_DDC, HDMI_HPD, HDMI_HPD_R
net class LVDS: LVDS0_CLK_N, LVDS0_CLK_P, LVDS0_TX0_N, LVDS0_TX0_P, LVDS0_TX1_N, LVDS0_TX1_P, LVDS0_TX2_N, LVDS0_TX2_P, LVDS0_TX3_N, LVDS0_TX3_P

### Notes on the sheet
- CPU - HDMI, LVDS
- DESIGN NOTE:
  HDMI_CEC signal has been moved to a new pin - software change is required. After reset this pin is output low by default.
- (near C76) 22mA
- HDMI
- DESIGN NOTE:
  Resistors R23, R157 are used as a divider to get a correct voltage on CPU HPD pin. This divider may not be required, as it looks like the HDMI_TX_HPD should be 5V tollerant, but it's not 100% clear from the documentation:
  HPD level:
  High: 2 - 5.3V
  Low: 0-0.8V
  Divider calculation:
  HDMI_HPD_R level =  HDMI_HPD level * R157 / (R23+R157) = 3.3 * 4k99 / (4k99+1k6) = 2.5V
  If the HDMI_HPD signal coming from the HDMI protection has 5V, you may want to use a different value of resistor R23 to achieve the correct value of the divider.
  If Hot plug detection is not working correctly replace R23 with 0R and do not fit R157. Testing is required.
- level 2V5 (5.3V tolerant)
- 19mA
- DESIGN NOTE:
  If HDMI CPU Output is not used, then leave HDMI_CEC_IN unconneced and enable the internal pulldown resistor on the pin HDMI_TX_CEC_LINE - pad H19.
- DESIGN NOTE:
  HDMI_DDCCEC - Analog ground reference for the Hot Plug detect signal.
  Place under the CPU if possible.
  from Design Guide: if HDMI_DDCCEC is unused, recommended condition is: leave floating
- LVDS
- FREE for personal and commercial use. See the license.
- Variant:
- Checked by
- Designed by www.fedevel.com

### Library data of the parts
C76 C77 C79 = C0603X5R0J224M030BB: as C61 on sheet [04] - CPU - PCIE, USB
C207 = C1005X5R1H104K: as C226 on sheet [17] - LVDS, CSI, LCD, TSC
C208 C246 C247 = C1005X5R1A475M: as C78 on sheet [04] - CPU - PCIE, USB
R21 R118 = RC0402FR-0747KL: RES 47.0K OHM 1/16W 1% 0402 SMD; Manufacturer: Yageo; Power (Watts): 0.063W, 1/16W; .Checked PCB: used; Temperature Coefficient: ±100ppm/°C
R23 = ERJ-2RKF1601X: RES 1.6K OHM 1/10W 1% 0402 SMD; Manufacturer: Panasonic Electronic Components; Power (Watts): 0.1W, 1/10W; Temperature Coefficient: ±100ppm/°C; .Creator: MM; .Checked PCB: used
R24-R27 R29 R36 = RC0402JR-070RL: as R33 on sheet [17] - LVDS, CSI, LCD, TSC
R32 = CRCW02011K60FKED: RES 1.60K OHM 1/20W 1% 0201 SMD; Manufacturer: Vishay Dale; Resistance (Ohms): 1.6k; Power (Watts): 0.05W, 1/20W; Temperature Coefficient: ±100ppm/°C; .Creator: MM
R157 = RMCF0402FT4K99: RES TF 4.99K OHM 1% 1/16W 0402; Manufacturer: Stackpole Electronics Inc; Power (Watts): 0.063W, 1/16W; .Checked PCB: used; Temperature Coefficient: ±100ppm/°C
U1 = MCIMX6Q5EYM10AC_v.ORX: as U1 on sheet [04] - CPU - PCIE, USB

## Sheet [06] - CPU - ETHERNET, SATA.SchDoc
size A2; DocumentNumber: 6; SheetNumber: 6; SheetTotal: 31
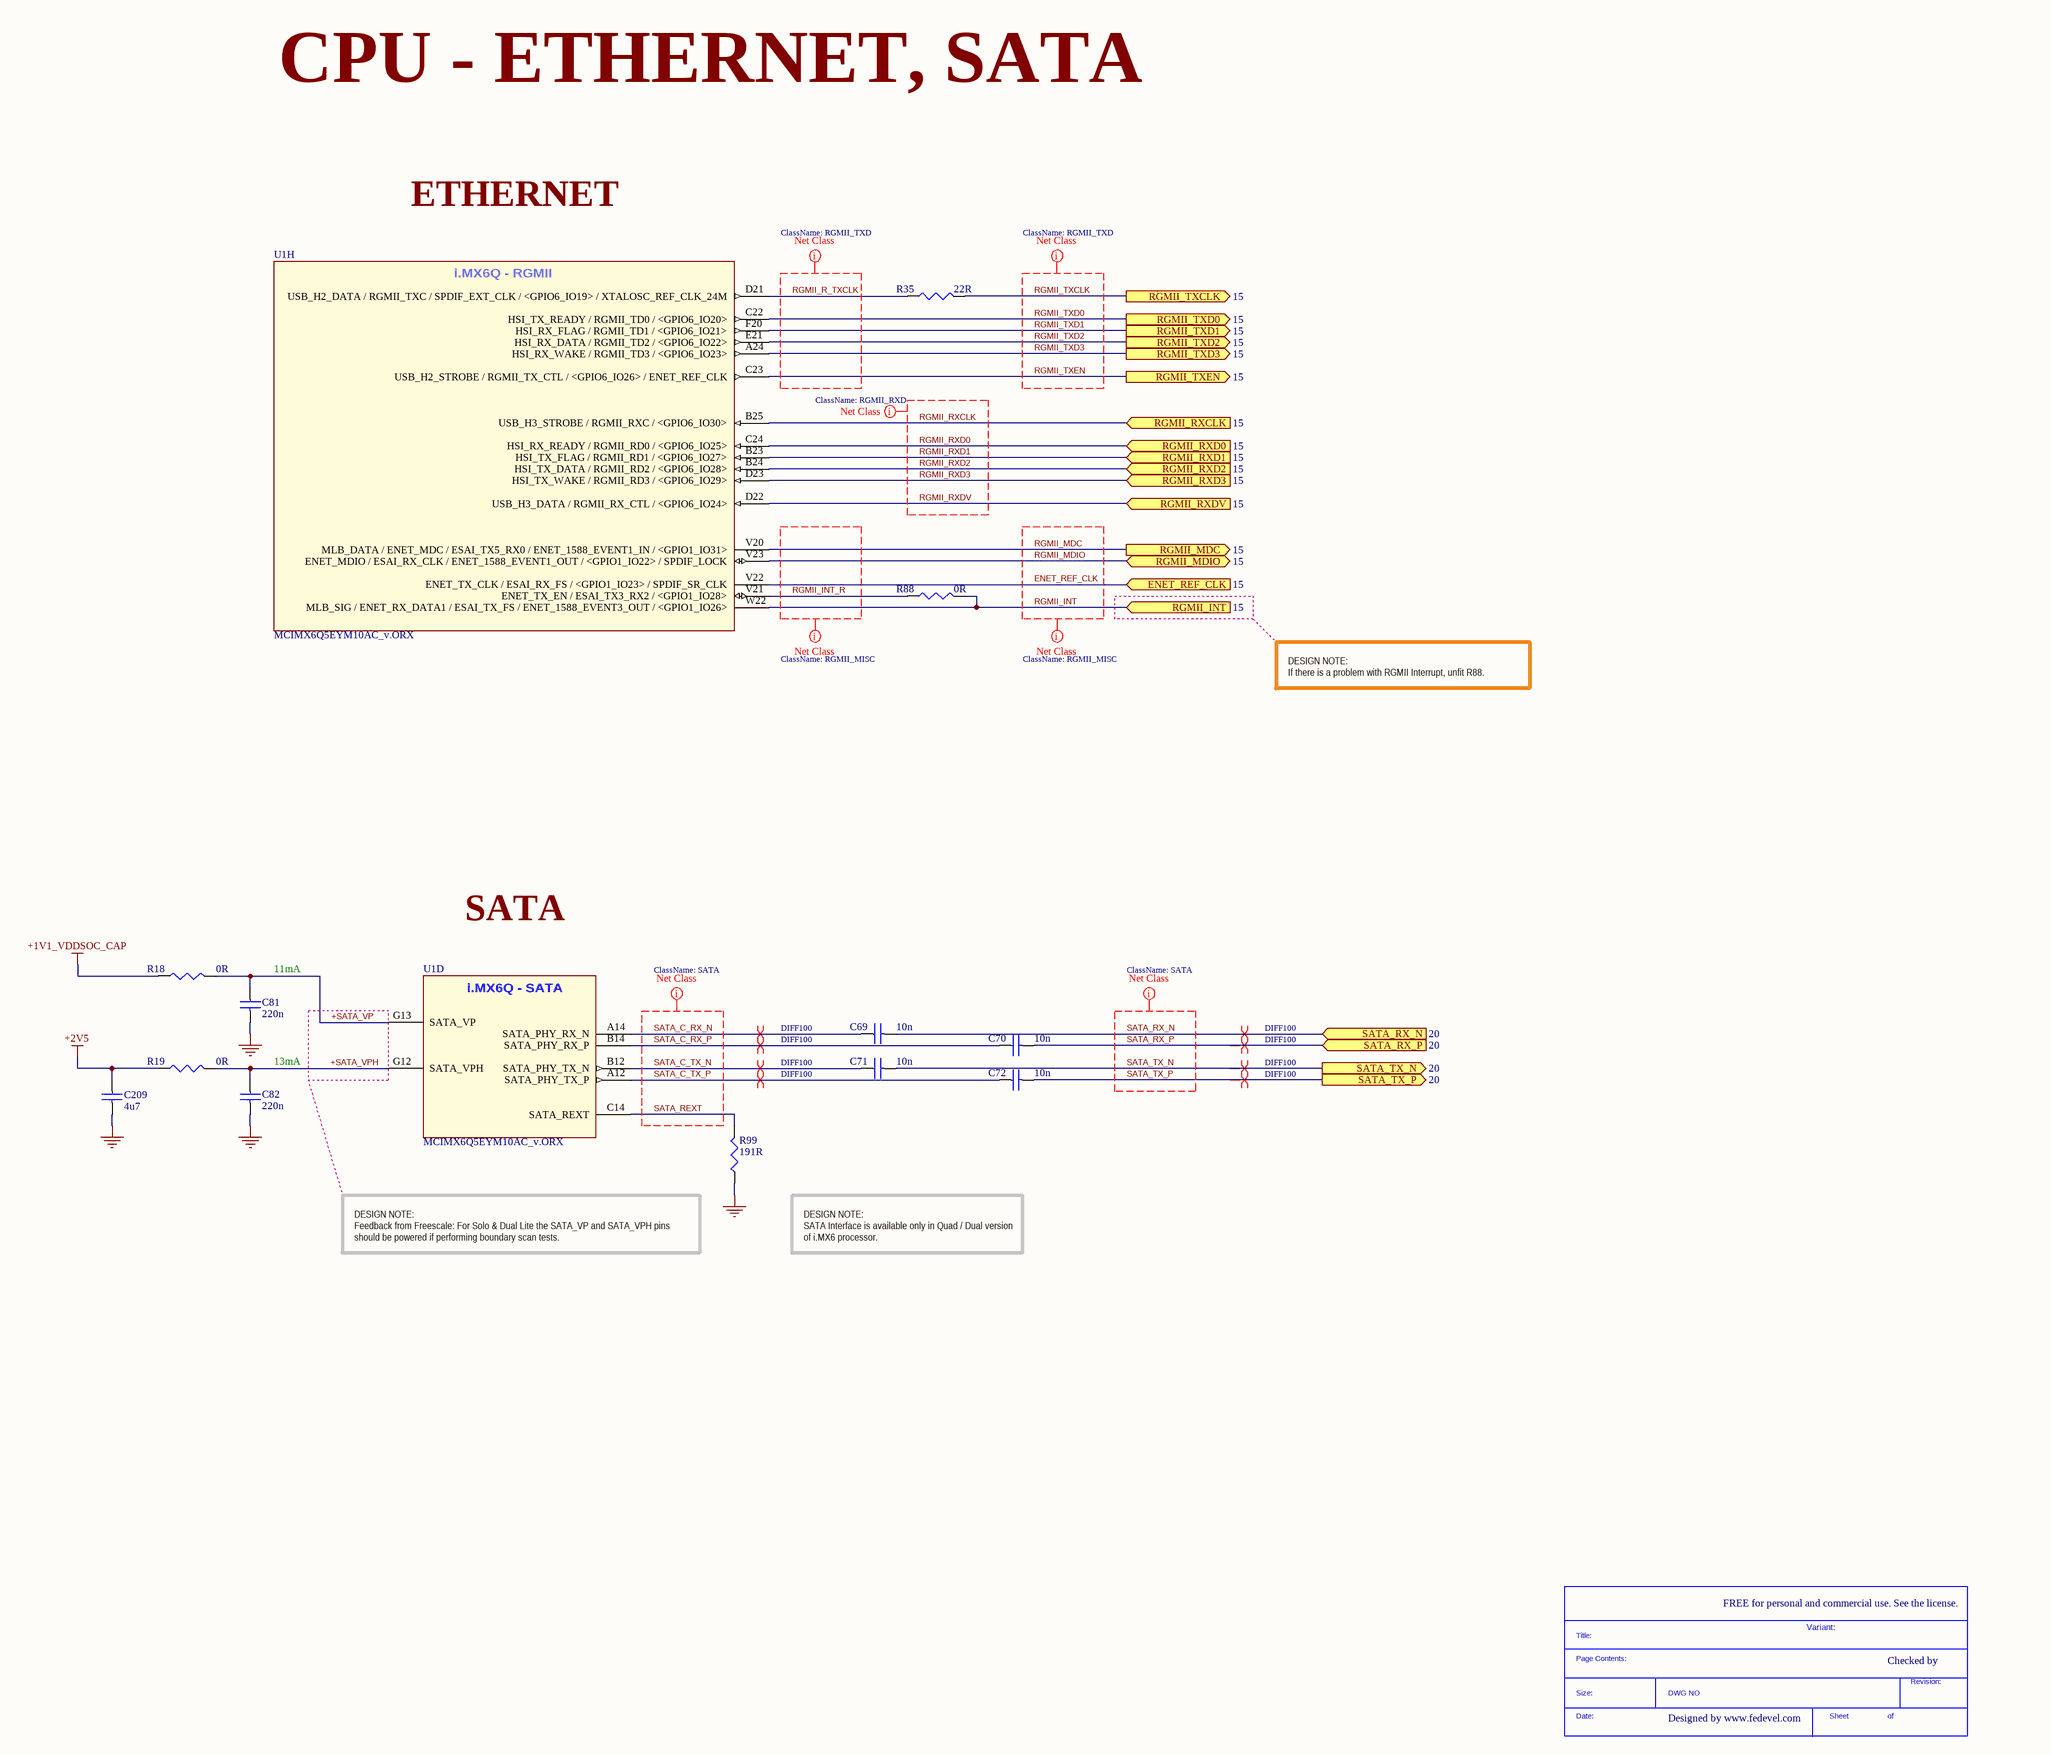
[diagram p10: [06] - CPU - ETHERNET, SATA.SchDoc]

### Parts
(Parts that share a designator on the sheet are numbered #1, #2 ... from top to bottom, then left to right.)
*#7  SDTitleBlock  (value not drawn)  (graphical)
C69  10n  [C0402]
C70  10n  [C0402]
C71  10n  [C0402]
C72  10n  [C0402]
C81  220n  [C0201]
C82  220n  [C0201]
C209  4u7  [C0402]
R18  0R  [R0402]
R19  0R  [R0402]
R35  22R  [R0402]
R88  0R  [R0402]
R99  191R  [R0201]
U1  MCIMX6Q5EYM10AC_v.ORX  [PBGA624]  (parts D,H of 21)

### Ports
ENET_REF_CLK (in, see 15), RGMII_INT (in, see 15), RGMII_MDC (out, see 15), RGMII_MDIO (bidir, see 15), RGMII_RXCLK (in, see 15), RGMII_RXD0 (in, see 15), RGMII_RXD1 (in, see 15), RGMII_RXD2 (in, see 15), RGMII_RXD3 (in, see 15), RGMII_RXDV (in, see 15), RGMII_TXCLK (out, see 15), RGMII_TXD0 (out, see 15), RGMII_TXD1 (out, see 15), RGMII_TXD2 (out, see 15), RGMII_TXD3 (out, see 15), RGMII_TXEN (out, see 15), SATA_RX_N (in, see 20), SATA_RX_P (in, see 20), SATA_TX_N (out, see 20), SATA_TX_P (out, see 20)

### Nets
+1V1_VDDSOC_CAP: R18.1
+2V5: C209.1 R19.1
GND: C81.2 C82.2 C209.2 R99.1
+SATA_VP: C81.1 R18.2 U1.G13(SATA_VP)
+SATA_VPH: C82.1 R19.2 U1.G12(SATA_VPH)
ENET_REF_CLK: U1.V22(ENET_TX_CLK_/_ESAI_RX_FS_/_<GPIO1_IO23>_/_SPDIF_SR_CLK) ; port ENET_REF_CLK
RGMII_INT: R88.2 U1.W22(MLB_SIG_/_ENET_RX_DATA1_/_ESAI_TX_FS_/_ENET_1588_EVENT3_OUT_/_<GPIO1_IO26>) ; port RGMII_INT
RGMII_INT_R: R88.1 U1.V21(ENET_TX_EN_/_ESAI_TX3_RX2_/_<GPIO1_IO28>)
RGMII_MDC: U1.V20(MLB_DATA_/_ENET_MDC_/_ESAI_TX5_RX0_/_ENET_1588_EVENT1_IN_/_<GPIO1_IO31>) ; port RGMII_MDC
RGMII_MDIO: U1.V23(ENET_MDIO_/_ESAI_RX_CLK_/_ENET_1588_EVENT1_OUT_/_<GPIO1_IO22>_/_SPDIF_LOCK) ; port RGMII_MDIO
RGMII_R_TXCLK: R35.1 U1.D21(USB_H2_DATA_/_RGMII_TXC_/_SPDIF_EXT_CLK_/_<GPIO6_IO19>_/_XTALOSC_REF_CLK_24M)
RGMII_RXCLK: U1.B25(USB_H3_STROBE_/_RGMII_RXC_/_<GPIO6_IO30>) ; port RGMII_RXCLK
RGMII_RXD0: U1.C24(HSI_RX_READY_/_RGMII_RD0_/_<GPIO6_IO25>) ; port RGMII_RXD0
RGMII_RXD1: U1.B23(HSI_TX_FLAG_/_RGMII_RD1_/_<GPIO6_IO27>) ; port RGMII_RXD1
RGMII_RXD2: U1.B24(HSI_TX_DATA_/_RGMII_RD2_/_<GPIO6_IO28>) ; port RGMII_RXD2
RGMII_RXD3: U1.D23(HSI_TX_WAKE_/_RGMII_RD3_/_<GPIO6_IO29>) ; port RGMII_RXD3
RGMII_RXDV: U1.D22(USB_H3_DATA_/_RGMII_RX_CTL_/_<GPIO6_IO24>) ; port RGMII_RXDV
RGMII_TXCLK: R35.2 ; port RGMII_TXCLK
RGMII_TXD0: U1.C22(HSI_TX_READY_/_RGMII_TD0_/_<GPIO6_IO20>) ; port RGMII_TXD0
RGMII_TXD1: U1.F20(HSI_RX_FLAG_/_RGMII_TD1_/_<GPIO6_IO21>) ; port RGMII_TXD1
RGMII_TXD2: U1.E21(HSI_RX_DATA_/_RGMII_TD2_/_<GPIO6_IO22>) ; port RGMII_TXD2
RGMII_TXD3: U1.A24(HSI_RX_WAKE_/_RGMII_TD3_/_<GPIO6_IO23>) ; port RGMII_TXD3
RGMII_TXEN: U1.C23(USB_H2_STROBE_/_RGMII_TX_CTL_/_<GPIO6_IO26>_/_ENET_REF_CLK) ; port RGMII_TXEN
SATA_C_RX_N: C69.1 U1.A14(SATA_PHY_RX_N)
SATA_C_RX_P: C70.1 U1.B14(SATA_PHY_RX_P)
SATA_C_TX_N: C71.1 U1.B12(SATA_PHY_TX_N)
SATA_C_TX_P: C72.1 U1.A12(SATA_PHY_TX_P)
SATA_REXT: R99.2 U1.C14(SATA_REXT)
SATA_RX_N: C69.2 ; port SATA_RX_N
SATA_RX_P: C70.2 ; port SATA_RX_P
SATA_TX_N: C71.2 ; port SATA_TX_N
SATA_TX_P: C72.2 ; port SATA_TX_P

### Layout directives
net class RGMII_MISC: ENET_REF_CLK, RGMII_INT, RGMII_INT_R, RGMII_MDC, RGMII_MDIO
net class RGMII_TXD: RGMII_R_TXCLK, RGMII_TXCLK, RGMII_TXD0, RGMII_TXD1, RGMII_TXD2, RGMII_TXD3, RGMII_TXEN
net class RGMII_RXD: RGMII_RXCLK, RGMII_RXD0, RGMII_RXD1, RGMII_RXD2, RGMII_RXD3, RGMII_RXDV
differential pair; net class DIFF100: SATA_C_RX_N, SATA_C_RX_P, SATA_C_TX_N, SATA_C_TX_P, SATA_RX_N, SATA_RX_P, SATA_TX_N, SATA_TX_P
net class SATA: SATA_C_RX_N, SATA_C_RX_P, SATA_C_TX_N, SATA_C_TX_P, SATA_REXT, SATA_RX_N, SATA_RX_P, SATA_TX_N, SATA_TX_P

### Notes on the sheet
- CPU - ETHERNET, SATA
- ETHERNET
- DESIGN NOTE:
  If there is a problem with RGMII Interrupt, unfit R88.
- SATA
- (near C81) 11mA
- 13mA
- DESIGN NOTE:
  Feedback from Freescale: For Solo & Dual Lite the SATA_VP and SATA_VPH pins should be powered if performing boundary scan tests.
- DESIGN NOTE:
  SATA Interface is available only in Quad / Dual version of i.MX6 processor.
- FREE for personal and commercial use. See the license.
- Variant:
- Checked by
- Designed by www.fedevel.com

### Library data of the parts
C69-C72 = C1005X7R1H103K: CAP CER 10000PF 50V 10% X7R 0402; Manufacturer: TDK Corporation; Value: 10nF; .Checked PCB: used
C81 C82 = C0603X5R0J224M030BB: as C61 on sheet [04] - CPU - PCIE, USB
C209 = C1005X5R1A475M: as C78 on sheet [04] - CPU - PCIE, USB
R18 R19 R88 = RC0402JR-070RL: as R33 on sheet [17] - LVDS, CSI, LCD, TSC
R35 = RC0402FR-0722RL: as R275 on sheet [17] - LVDS, CSI, LCD, TSC
R99 = ERJ-1GEF1910C: RES 191 OHM 1/20W 1% 0201 SMD; Manufacturer: Panasonic Electronic Components; Resistance (Ohms): 191; Power (Watts): 0.05W, 1/20W; Temperature Coefficient: ±200ppm/°C; .Creator: MM
U1 = MCIMX6Q5EYM10AC_v.ORX: as U1 on sheet [04] - CPU - PCIE, USB

## Sheet [08] - CPU - SPI, UART.SchDoc
size A2; DocumentNumber: 8; SheetNumber: 8; SheetTotal: 31
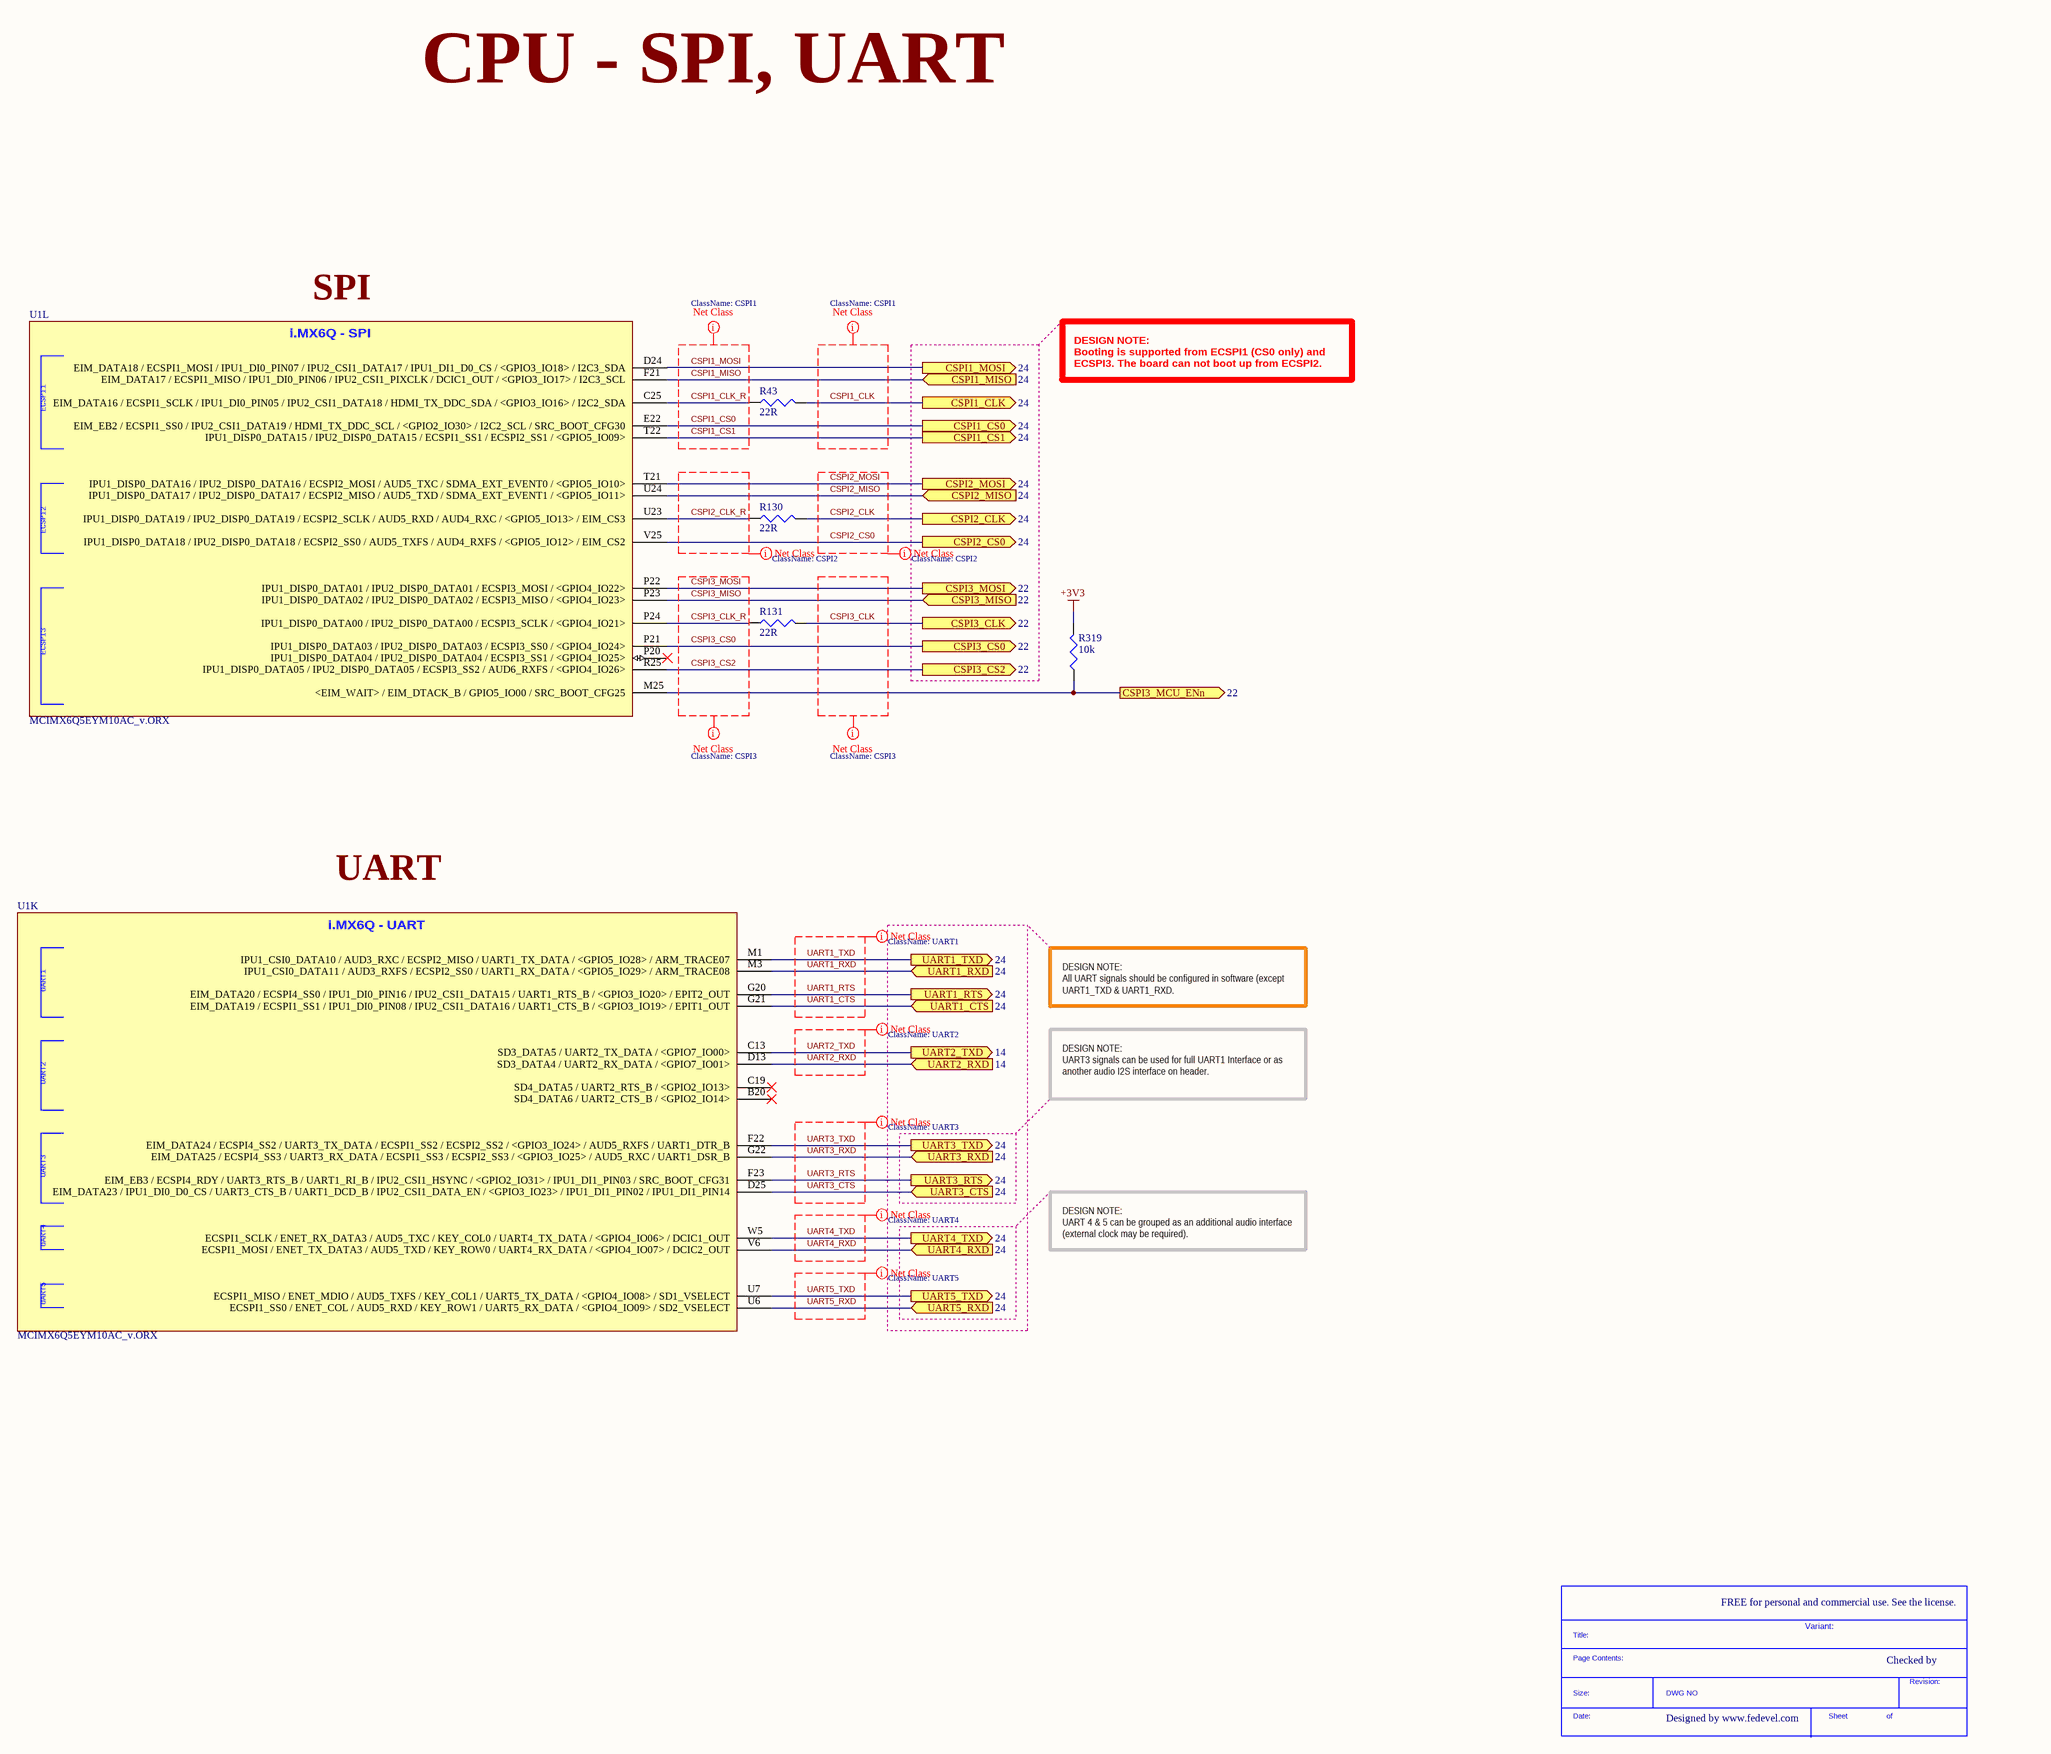
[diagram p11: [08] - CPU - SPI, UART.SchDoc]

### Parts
(Parts that share a designator on the sheet are numbered #1, #2 ... from top to bottom, then left to right.)
*#8  SDTitleBlock  (value not drawn)  (graphical)
R43  22R  [R0402]
R130  22R  [R0402]
R131  22R  [R0402]
R319  10k  [R0402]
U1  MCIMX6Q5EYM10AC_v.ORX  [PBGA624]  (parts K,L of 21)

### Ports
CSPI1_CLK (out, see 24), CSPI1_CS0 (out, see 24), CSPI1_CS1 (out, see 24), CSPI1_MISO (in, see 24), CSPI1_MOSI (out, see 24), CSPI2_CLK (out, see 24), CSPI2_CS0 (out, see 24), CSPI2_MISO (in, see 24), CSPI2_MOSI (out, see 24), CSPI3_CLK (see 22), CSPI3_CS0 (out, see 22), CSPI3_CS2 (out, see 22), CSPI3_MCU_ENn (out, see 22), CSPI3_MISO (in, see 22), CSPI3_MOSI (see 22), UART1_CTS (in, see 24), UART1_RTS (out, see 24), UART1_RXD (in, see 24), UART1_TXD (out, see 24), UART2_RXD (in, see 14), UART2_TXD (out, see 14), UART3_CTS (in, see 24), UART3_RTS (out, see 24), UART3_RXD (in, see 24), UART3_TXD (out, see 24), UART4_RXD (in, see 24), UART4_TXD (out, see 24), UART5_RXD (in, see 24), UART5_TXD (out, see 24)

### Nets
+3V3: R319.2
CSPI1_CLK: R43.2 ; port CSPI1_CLK
CSPI1_CLK_R: R43.1 U1.C25(EIM_DATA16_/_ECSPI1_SCLK_/_IPU1_DI0_PIN05_/_IPU2_CSI1_DATA18_/_HDMI_TX_DDC_SDA_/_<GPIO3_IO16>_/_I2C2_SDA)
CSPI1_CS0: U1.E22(EIM_EB2_/_ECSPI1_SS0_/_IPU2_CSI1_DATA19_/_HDMI_TX_DDC_SCL_/_<GPIO2_IO30>_/_I2C2_SCL_/_SRC_BOOT_CFG30) ; port CSPI1_CS0
CSPI1_CS1: U1.T22(IPU1_DISP0_DATA15_/_IPU2_DISP0_DATA15_/_ECSPI1_SS1_/_ECSPI2_SS1_/_<GPIO5_IO09>) ; port CSPI1_CS1
CSPI1_MISO: U1.F21(EIM_DATA17_/_ECSPI1_MISO_/_IPU1_DI0_PIN06_/_IPU2_CSI1_PIXCLK_/_DCIC1_OUT_/_<GPIO3_IO17>_/_I2C3_SCL) ; port CSPI1_MISO
CSPI1_MOSI: U1.D24(EIM_DATA18_/_ECSPI1_MOSI_/_IPU1_DI0_PIN07_/_IPU2_CSI1_DATA17_/_IPU1_DI1_D0_CS_/_<GPIO3_IO18>_/_I2C3_SDA) ; port CSPI1_MOSI
CSPI2_CLK: R130.2 ; port CSPI2_CLK
CSPI2_CLK_R: R130.1 U1.U23(IPU1_DISP0_DATA19_/_IPU2_DISP0_DATA19_/_ECSPI2_SCLK_/_AUD5_RXD_/_AUD4_RXC_/_<GPIO5_IO13>_/_EIM_CS3)
CSPI2_CS0: U1.V25(IPU1_DISP0_DATA18_/_IPU2_DISP0_DATA18_/_ECSPI2_SS0_/_AUD5_TXFS_/_AUD4_RXFS_/_<GPIO5_IO12>_/_EIM_CS2) ; port CSPI2_CS0
CSPI2_MISO: U1.U24(IPU1_DISP0_DATA17_/_IPU2_DISP0_DATA17_/_ECSPI2_MISO_/_AUD5_TXD_/_SDMA_EXT_EVENT1_/_<GPIO5_IO11>) ; port CSPI2_MISO
CSPI2_MOSI: U1.T21(IPU1_DISP0_DATA16_/_IPU2_DISP0_DATA16_/_ECSPI2_MOSI_/_AUD5_TXC_/_SDMA_EXT_EVENT0_/_<GPIO5_IO10>) ; port CSPI2_MOSI
CSPI3_CLK: R131.2 ; port CSPI3_CLK
CSPI3_CLK_R: R131.1 U1.P24(IPU1_DISP0_DATA00_/_IPU2_DISP0_DATA00_/_ECSPI3_SCLK_/_<GPIO4_IO21>)
CSPI3_CS0: U1.P21(IPU1_DISP0_DATA03_/_IPU2_DISP0_DATA03_/_ECSPI3_SS0_/_<GPIO4_IO24>) ; port CSPI3_CS0
CSPI3_CS2: U1.R25(IPU1_DISP0_DATA05_/_IPU2_DISP0_DATA05_/_ECSPI3_SS2_/_AUD6_RXFS_/_<GPIO4_IO26>) ; port CSPI3_CS2
CSPI3_MCU_ENn: R319.1 U1.M25(<EIM_WAIT>_/_EIM_DTACK_B_/_GPIO5_IO00_/_SRC_BOOT_CFG25) ; port CSPI3_MCU_ENn
CSPI3_MISO: U1.P23(IPU1_DISP0_DATA02_/_IPU2_DISP0_DATA02_/_ECSPI3_MISO_/_<GPIO4_IO23>) ; port CSPI3_MISO
CSPI3_MOSI: U1.P22(IPU1_DISP0_DATA01_/_IPU2_DISP0_DATA01_/_ECSPI3_MOSI_/_<GPIO4_IO22>) ; port CSPI3_MOSI
UART1_CTS: U1.G21(EIM_DATA19_/_ECSPI1_SS1_/_IPU1_DI0_PIN08_/_IPU2_CSI1_DATA16_/_UART1_CTS_B_/_<GPIO3_IO19>_/_EPIT1_OUT) ; port UART1_CTS
UART1_RTS: U1.G20(EIM_DATA20_/_ECSPI4_SS0_/_IPU1_DI0_PIN16_/_IPU2_CSI1_DATA15_/_UART1_RTS_B_/_<GPIO3_IO20>_/_EPIT2_OUT) ; port UART1_RTS
UART1_RXD: U1.M3(IPU1_CSI0_DATA11_/_AUD3_RXFS_/_ECSPI2_SS0_/_UART1_RX_DATA_/_<GPIO5_IO29>_/_ARM_TRACE08) ; port UART1_RXD
UART1_TXD: U1.M1(IPU1_CSI0_DATA10_/_AUD3_RXC_/_ECSPI2_MISO_/_UART1_TX_DATA_/_<GPIO5_IO28>_/_ARM_TRACE07) ; port UART1_TXD
UART2_RXD: U1.D13(SD3_DATA4_/_UART2_RX_DATA_/_<GPIO7_IO01>) ; port UART2_RXD
UART2_TXD: U1.C13(SD3_DATA5_/_UART2_TX_DATA_/_<GPIO7_IO00>) ; port UART2_TXD
UART3_CTS: U1.D25(EIM_DATA23_/_IPU1_DI0_D0_CS_/_UART3_CTS_B_/_UART1_DCD_B_/_IPU2_CSI1_DATA_EN_/_<GPIO3_IO23>_/_IPU1_DI1_PIN02_/_IPU1_DI1_PIN14) ; port UART3_CTS
UART3_RTS: U1.F23(EIM_EB3_/_ECSPI4_RDY_/_UART3_RTS_B_/_UART1_RI_B_/_IPU2_CSI1_HSYNC_/_<GPIO2_IO31>_/_IPU1_DI1_PIN03_/_SRC_BOOT_CFG31) ; port UART3_RTS
UART3_RXD: U1.G22(EIM_DATA25_/_ECSPI4_SS3_/_UART3_RX_DATA_/_ECSPI1_SS3_/_ECSPI2_SS3_/_<GPIO3_IO25>_/_AUD5_RXC_/_UART1_DSR_B) ; port UART3_RXD
UART3_TXD: U1.F22(EIM_DATA24_/_ECSPI4_SS2_/_UART3_TX_DATA_/_ECSPI1_SS2_/_ECSPI2_SS2_/_<GPIO3_IO24>_/_AUD5_RXFS_/_UART1_DTR_B) ; port UART3_TXD
UART4_RXD: U1.V6(ECSPI1_MOSI_/_ENET_TX_DATA3_/_AUD5_TXD_/_KEY_ROW0_/_UART4_RX_DATA_/_<GPIO4_IO07>_/_DCIC2_OUT) ; port UART4_RXD
UART4_TXD: U1.W5(ECSPI1_SCLK_/_ENET_RX_DATA3_/_AUD5_TXC_/_KEY_COL0_/_UART4_TX_DATA_/_<GPIO4_IO06>_/_DCIC1_OUT) ; port UART4_TXD
UART5_RXD: U1.U6(ECSPI1_SS0_/_ENET_COL_/_AUD5_RXD_/_KEY_ROW1_/_UART5_RX_DATA_/_<GPIO4_IO09>_/_SD2_VSELECT) ; port UART5_RXD
UART5_TXD: U1.U7(ECSPI1_MISO_/_ENET_MDIO_/_AUD5_TXFS_/_KEY_COL1_/_UART5_TX_DATA_/_<GPIO4_IO08>_/_SD1_VSELECT) ; port UART5_TXD

Not connected (* = marked no-connect by the designer): U1 B20(SD4_DATA6_/_UART2_CTS_B_/_<GPIO2_IO14>)* C19(SD4_DATA5_/_UART2_RTS_B_/_<GPIO2_IO13>)* P20(IPU1_DISP0_DATA04_/_IPU2_DISP0_DATA04_/_ECSPI3_SS1_/_<GPIO4_IO25>)*

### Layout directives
net class UART1: UART1_CTS, UART1_RTS, UART1_RXD, UART1_TXD
net class CSPI1: CSPI1_CLK, CSPI1_CLK_R, CSPI1_CS0, CSPI1_CS1, CSPI1_MISO, CSPI1_MOSI
net class CSPI3: CSPI3_CLK, CSPI3_CLK_R, CSPI3_CS0, CSPI3_CS2, CSPI3_MISO, CSPI3_MOSI
net class UART3: UART3_CTS, UART3_RTS, UART3_RXD, UART3_TXD
net class CSPI2: CSPI2_CLK, CSPI2_CLK_R, CSPI2_CS0, CSPI2_MISO, CSPI2_MOSI
net class UART4: UART4_RXD, UART4_TXD
net class UART5: UART5_RXD, UART5_TXD
net class UART2: UART2_RXD, UART2_TXD

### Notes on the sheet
- CPU - SPI, UART
- SPI
- DESIGN NOTE:
  Booting is supported from ECSPI1 (CS0 only) and ECSPI3. The board can not boot up from ECSPI2.
- UART
- DESIGN NOTE:
  All UART signals should be configured in software (except UART1_TXD & UART1_RXD.
- DESIGN NOTE:
  UART3 signals can be used for full UART1 Interface or as another audio I2S interface on header.
- DESIGN NOTE:
  UART 4 & 5 can be grouped as an additional audio interface (external clock may be required).
- FREE for personal and commercial use. See the license.
- Variant:
- Checked by
- Designed by www.fedevel.com

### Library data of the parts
R43 R130 R131 = RC0402FR-0722RL: as R275 on sheet [17] - LVDS, CSI, LCD, TSC
R319 = RC0402FR-0710KL: as R52 on sheet [17] - LVDS, CSI, LCD, TSC
U1 = MCIMX6Q5EYM10AC_v.ORX: IC MCU 32BIT ARM QUAD 624FCBGA; Manufacturer: Freescale Semiconductor; Core Processor: ARM® Cortex™-A9; Core Size: 32-Bit Quad-Core; Speed: 1.0GHz; Connectivity: CAN, EBI/EMI, ESAI, Ethernet, GPMI, I2C, MMC/SD, PCI, SATA, SPI, UART, USB, USB OTG; Peripherals: DMA, HDMI, I2S/SSI/AC97, MIPI CSI, MIMI DSI, MIPI HIS, PWM, WDT; Number of I /O: 224; Program Memory Type: External Program Memory; RAM Size: 256K x 8; Voltage - Supply (Vcc/Vdd): 0.925 V ~ 1.5 V; Oscillator Type: Internal; .Creator: MM; .Checked PCB: MM, checked by RF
